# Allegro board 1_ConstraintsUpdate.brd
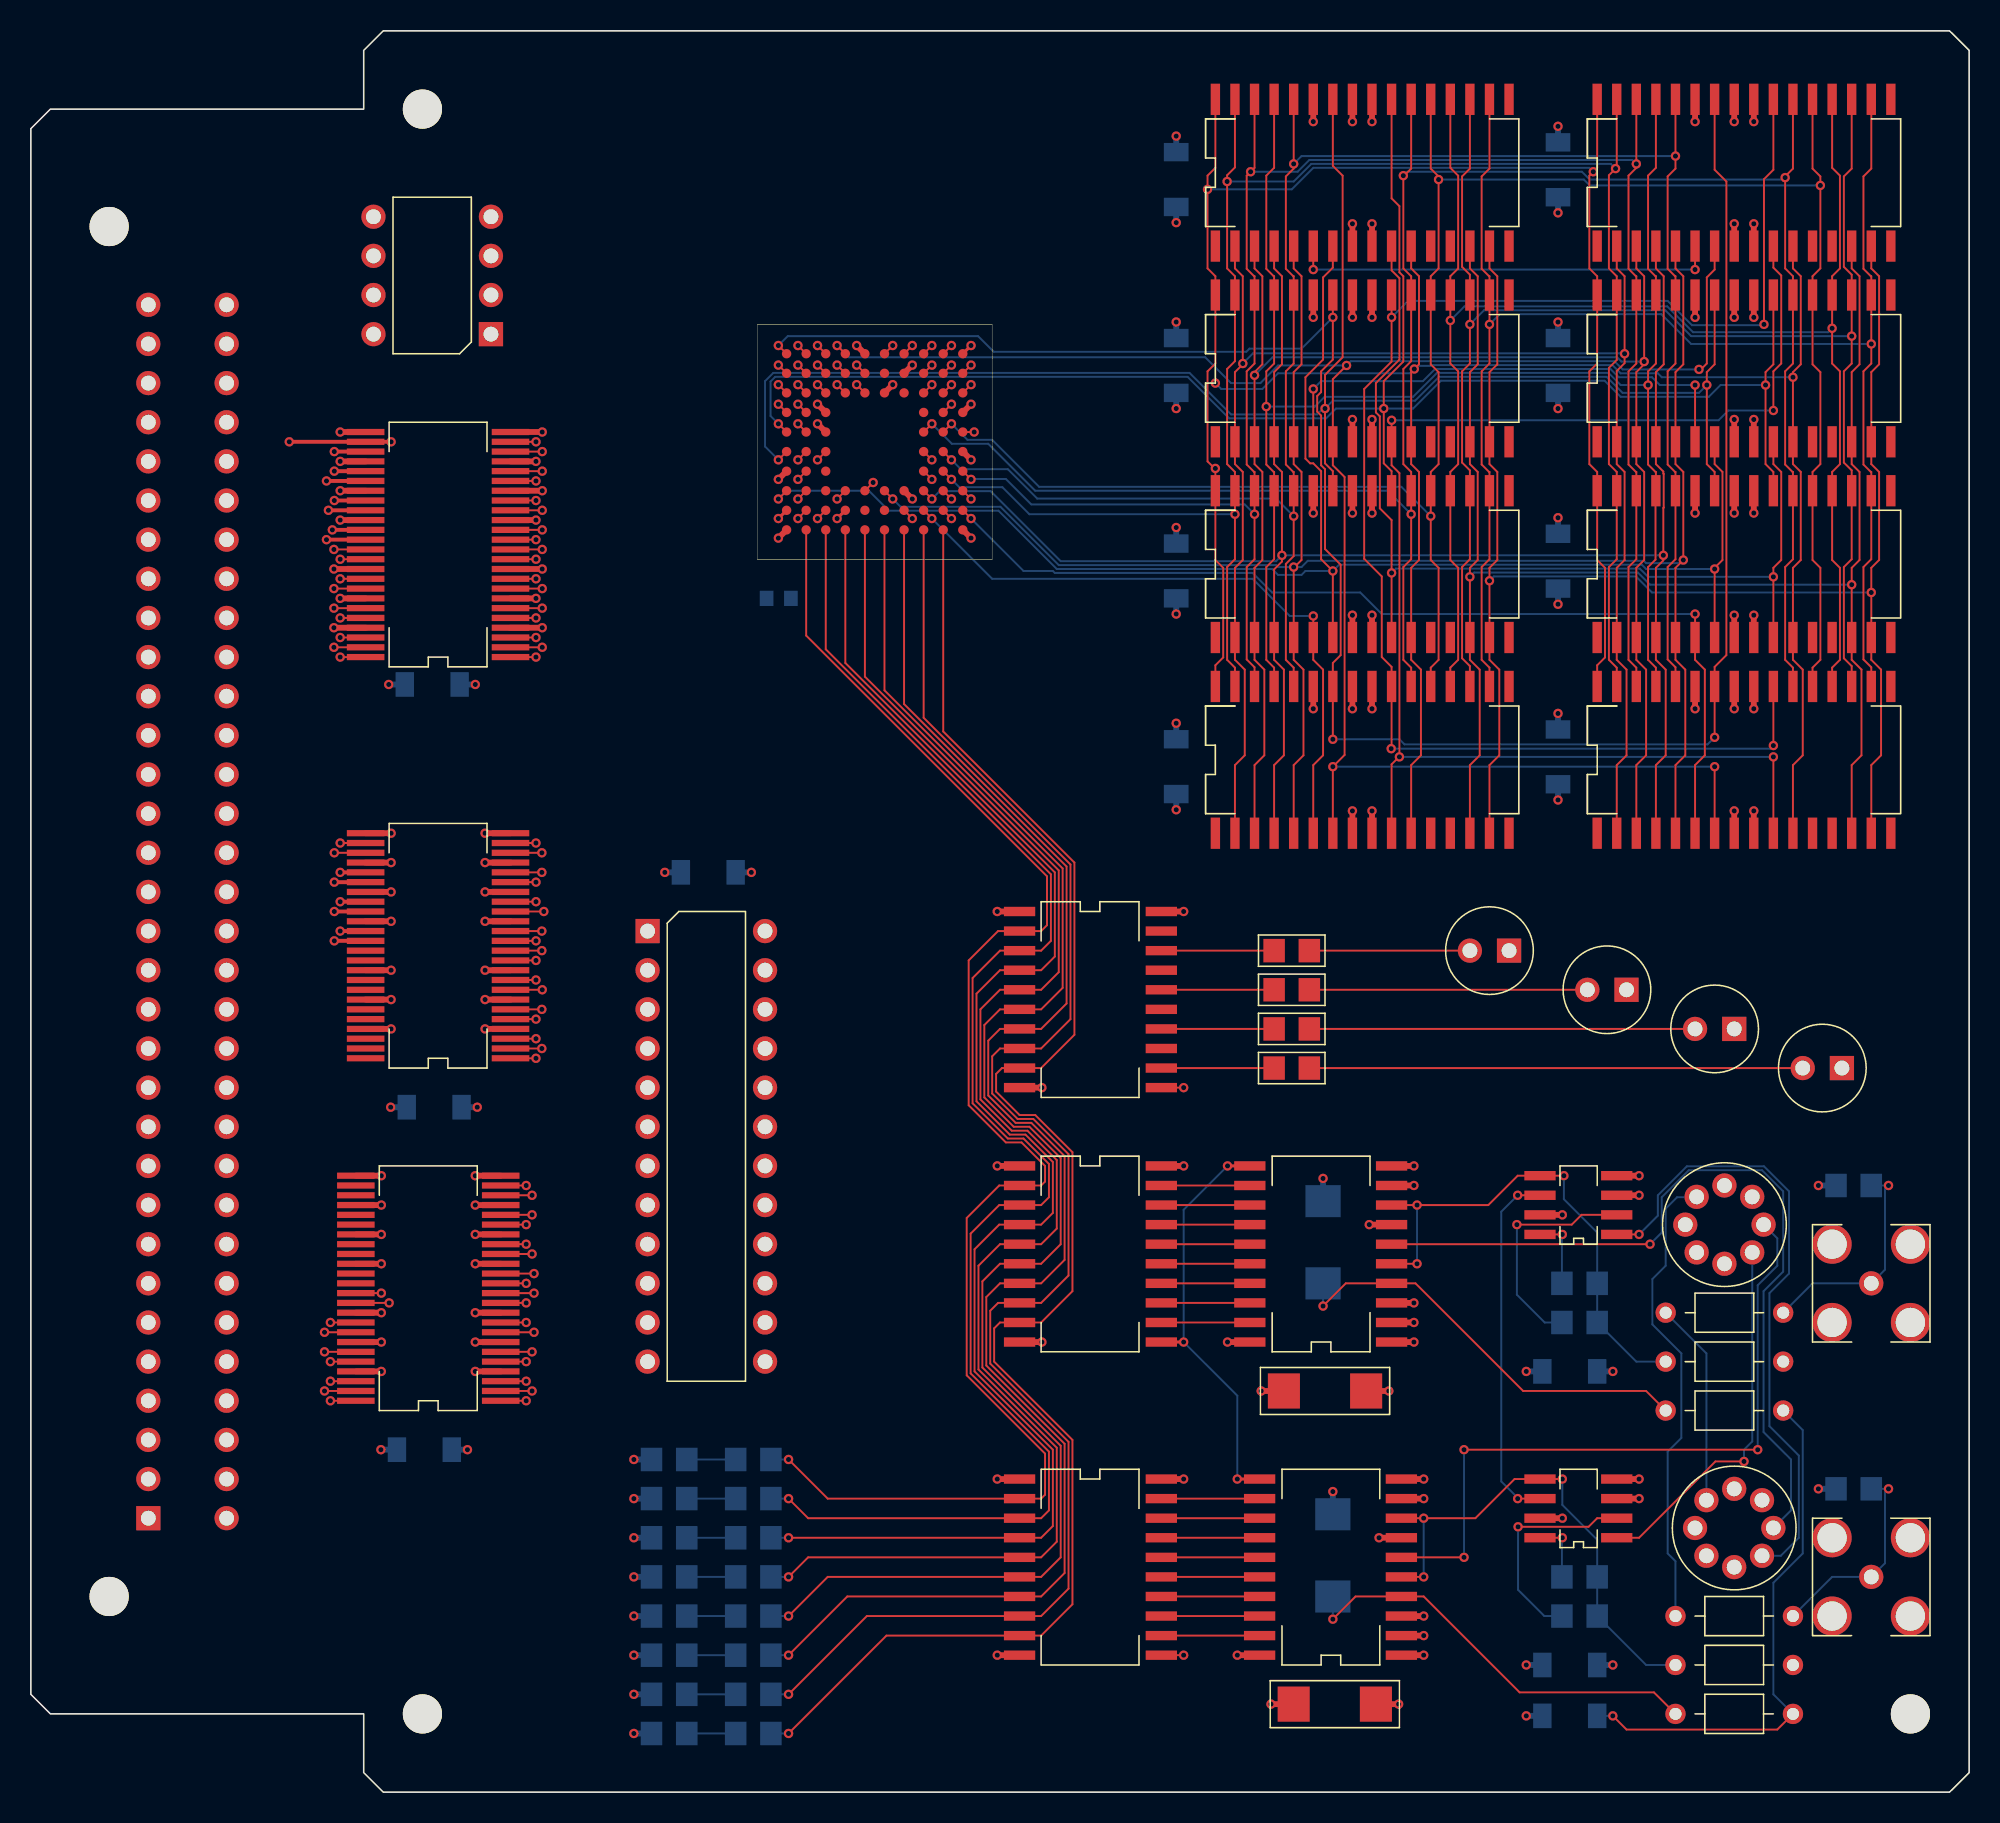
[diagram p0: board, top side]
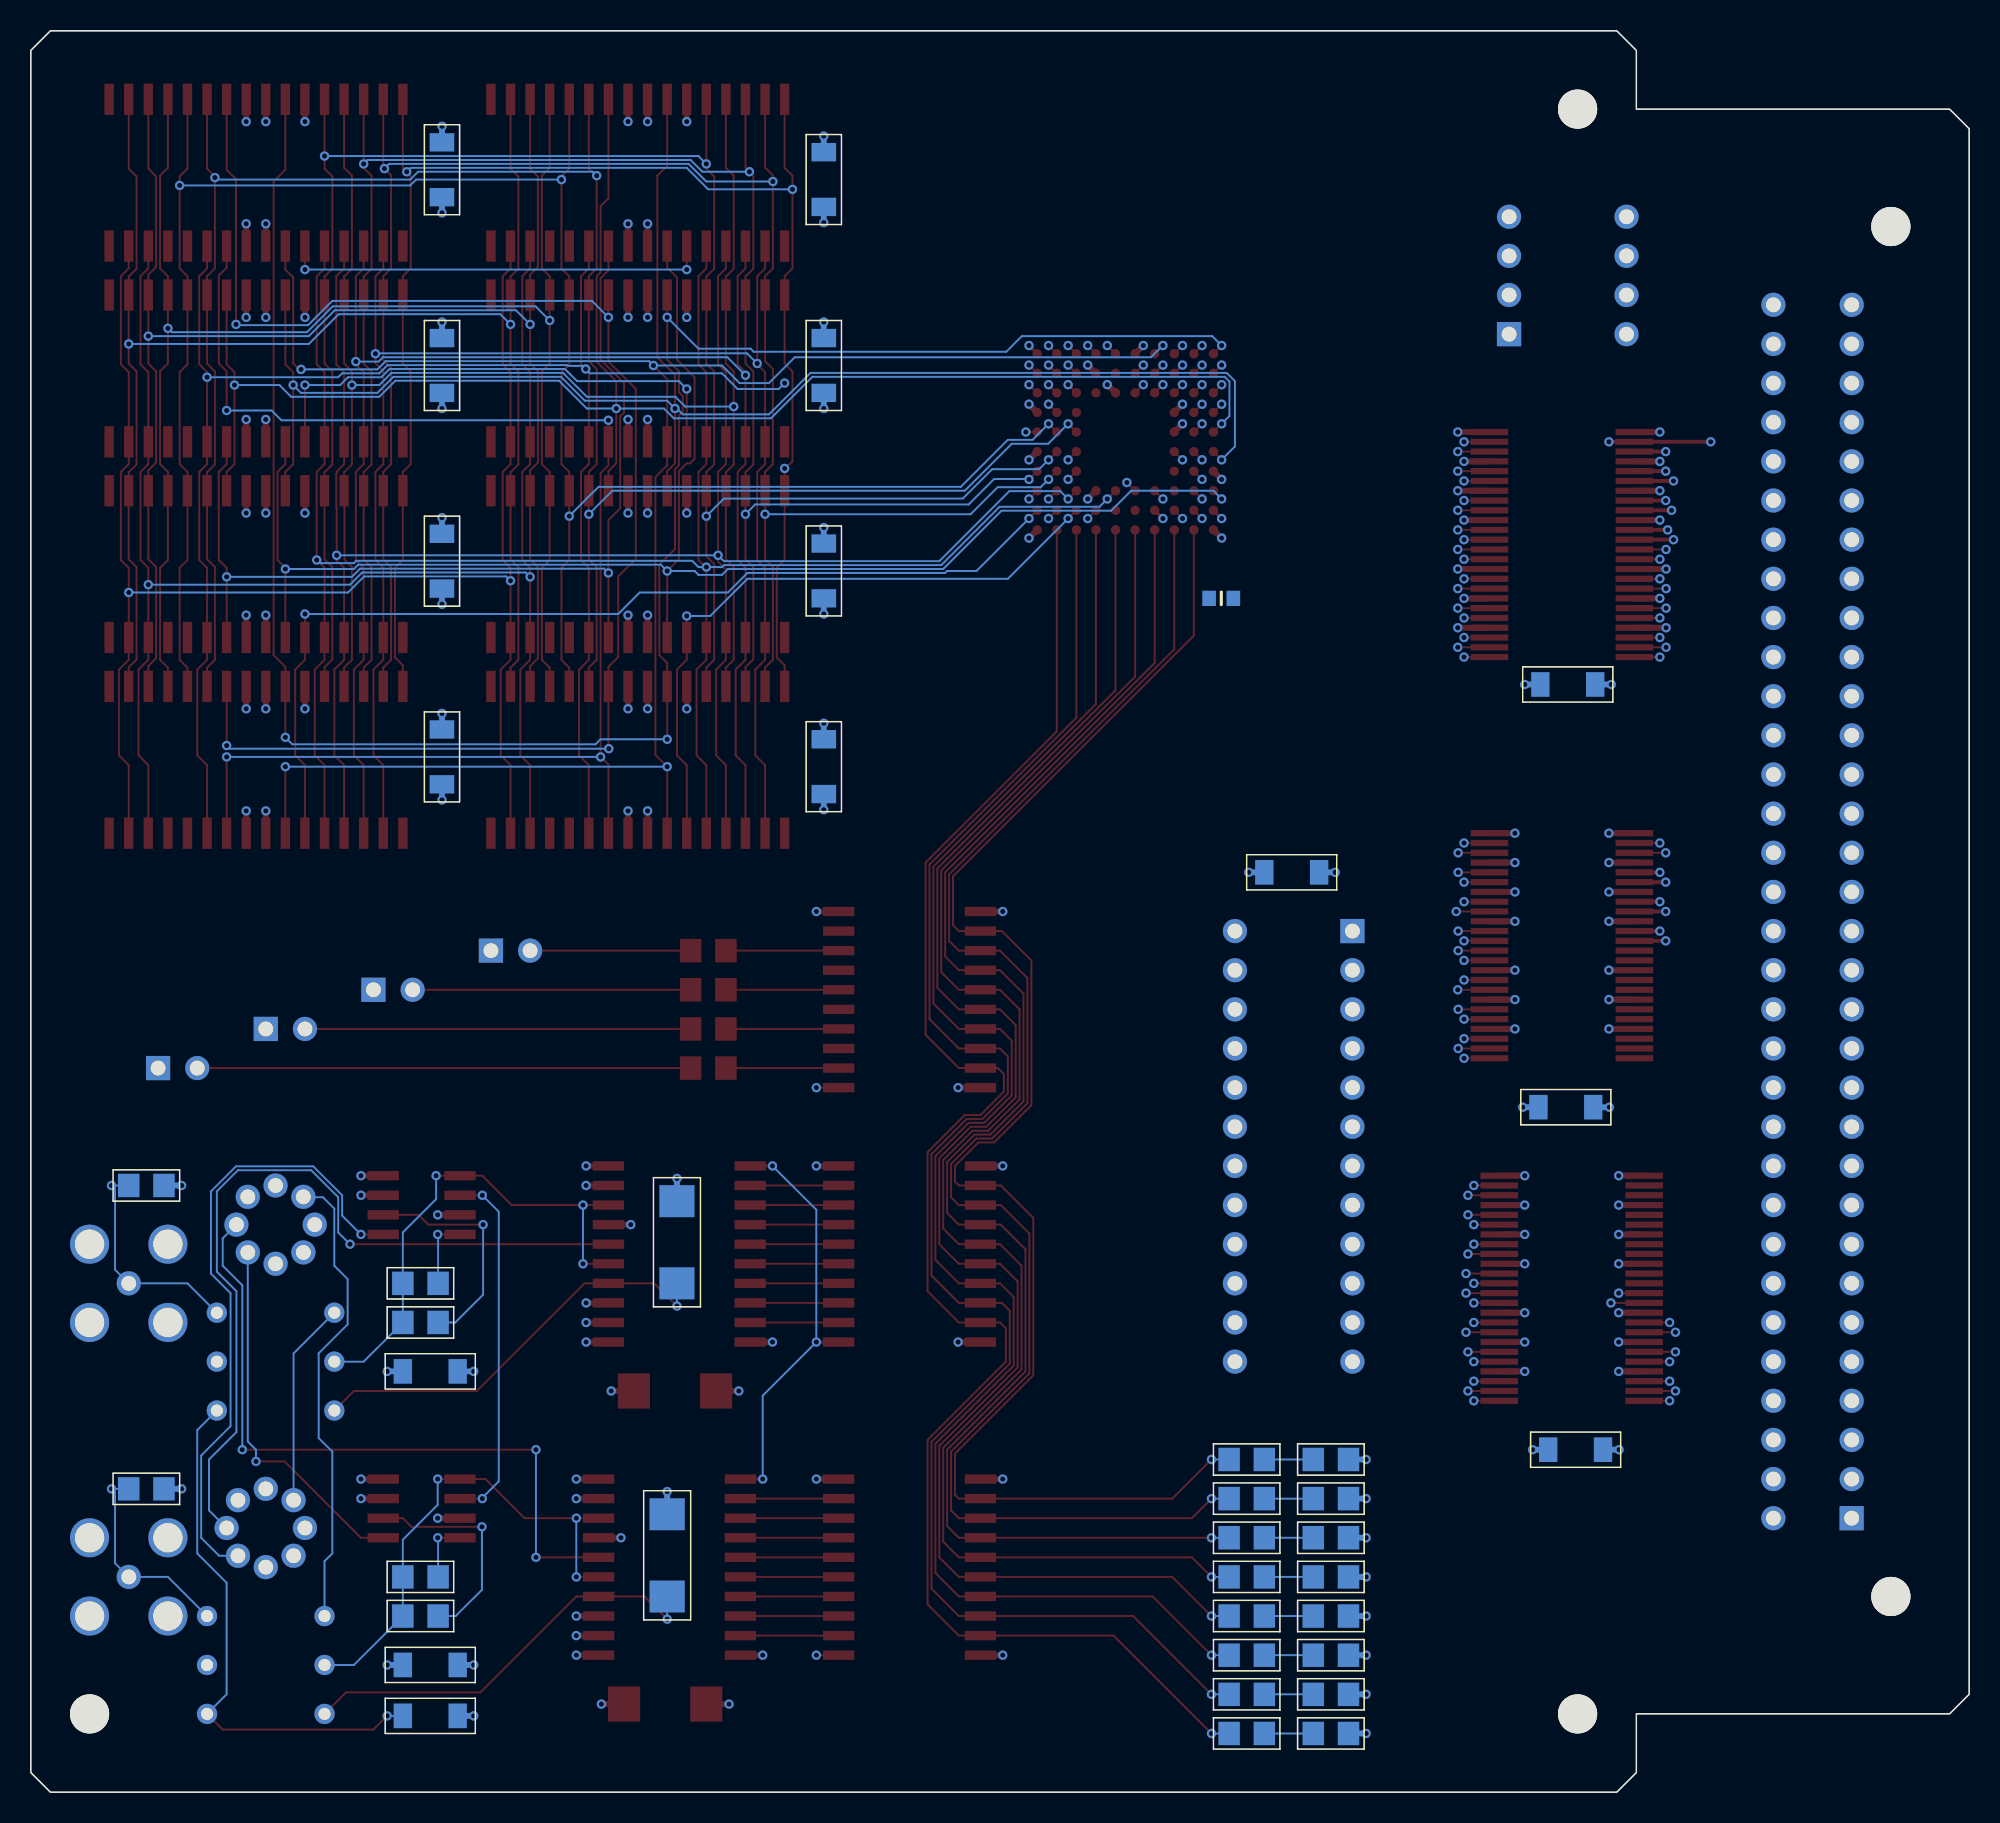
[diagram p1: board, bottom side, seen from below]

Outline 125.73 x 114.3 mm; copper layers: TOP, GND, INNER_1, INNER_2, VCC, BOTTOM. Coordinates in mm from the lower left corner of the outline.

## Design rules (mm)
constraint set DEFAULT: min track width 0.127
net group BNC2: nets BNC2 OUTA
net group BNC3: nets BNC3 OUTB
net group Q0: nets Q0 Q1
net group Q2: nets Q2 Q3
net group Q4: nets Q4 Q5
net group Q6: nets Q6 Q7
net group VCLKC: nets N1626465 VCLKC
net group VD0: nets N14855 VD0
net group VD1: nets N14853 VD1
net group VD2: nets N14849 VD2
net group VD3: nets N14843 VD3
net group VD4: nets N15161 VD4
net group VD5: nets N15155 VD5
net group VD6: nets N15151 VD6
net group VD7: nets N15143 VD7
net group CLOCK_NETS: nets DCLK MCLK VCLKA
net group DC_NETS: nets AGND GND GND_EARTH V12N V+12 VCC
net group N00036_DATA_DAAMP: nets N00036_DATA_DAAMP N282866_DATA_DAAMP N282912_DATA_DAAMP
net group N00036_DATA_DAAMP0: nets N00036_DATA_DAAMP0 N282866_DATA_DAAMP0 N282912_DATA_DAAMP0
net group VREF: nets N00038_DATA_DAAMP N00038_DATA_DAAMP0 VREF

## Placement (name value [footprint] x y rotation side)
C1  0.1uF  [SM_1206]  27.3 22.23 180 bottom
C2  0.1uF  [SM_1206]  27.94 44.45 180 bottom
C3  0.1uF  [SM_1206]  27.81 71.88 180 bottom
C4  0.1uF  [SM_1206]  45.72 59.69 180 bottom
C5  47PF  [SM_0805]  119.38 39.37 180 bottom
C6  47PF  [SM_0805]  119.38 19.69 180 bottom
C7  3300  [SM_0805]  42.55 6.35 180 bottom
C8  3300  [SM_0805]  42.55 11.43 180 bottom
C9  3300  [SM_0805]  42.55 16.51 180 bottom
C10  3300  [SM_0805]  42.55 21.59 180 bottom
C11  3300  [SM_0805]  42.55 3.81 180 bottom
C12  3300  [SM_0805]  42.55 8.89 180 bottom
C13  3300  [SM_0805]  42.55 13.97 180 bottom
C14  3300  [SM_0805]  42.55 19.05 180 bottom
C15  0.1uF  [SM_1206]  99.06 103.5 90 bottom
C16  0.1uF  [SM_1206]  99.06 78.11 90 bottom
C17  0.1uF  [SM_1206]  99.06 90.8 90 bottom
C18  0.1uF  [SM_1206]  74.3 102.87 90 bottom
C19  0.1uF  [SM_1206]  99.06 65.41 90 bottom
C20  0.1uF  [SM_1206]  74.3 90.8 90 bottom
C21  0.1uF  [SM_1206]  74.3 77.47 90 bottom
C22  0.1uF  [SM_1206]  74.3 64.77 90 bottom
C23  .01uF  [SMC_6032]  81.28 26.03 0 top
C24  .01uF  [SMC_6032]  83.82 33.02 90 bottom
C25  0.1uF  [SM_1206]  101.6 27.3 180 bottom
C26  .01uF  [SMC_6032]  81.91 5.71 0 top
C27  .01uF  [SMC_6032]  84.45 12.7 90 bottom
C28  0.1uF  [SM_1206]  101.6 8.25 180 bottom
D1  -  [LED]  95.88 54.61 180 top
D2  -  [LED]  103.5 52.07 180 top
D3  -  [LED]  110.49 49.53 180 top
D4  -  [LED]  117.47 46.99 180 top
J1  CON64  [DIN64]  7.62 17.78 0 top
J2  -  [BNC]  119.38 33.02 0 top
J3  -  [BNC]  119.38 13.97 0 top
L1  50  [IND300]  106.04 31.12 0 top
L2  50  [IND300]  106.68 11.43 0 top
L3  50  [IND300]  113.66 24.77 180 top
L4  50  [IND300]  113.66 27.94 180 top
L5  50  [IND300]  114.3 5.08 180 top
L6  50  [IND300]  114.3 8.25 180 top
NOREF  -  [unnamed]  25.4 5.08 0 top
NOREF#2  -  [#2]  259.08 129.54 0 top
NOREF#3  -  [#2]  -30.48 -55.88 0 top
R1  150  [SM_0805]  80.64 54.61 0 top
R2  150  [SM_0805]  80.64 52.07 0 top
R3  150  [SM_0805]  80.64 49.53 0 top
R4  150  [SM_0805]  80.64 46.99 0 top
R5  3.32 kOhm  [RESC1608X55N]  48.51 77.47 180 bottom
R6  10K  [SM_0805]  45.72 6.35 0 bottom
R7  10K  [SM_0805]  45.72 11.43 0 bottom
R8  10K  [SM_0805]  45.72 16.51 0 bottom
R9  10K  [SM_0805]  45.72 21.59 0 bottom
R10  10K  [SM_0805]  45.72 3.81 0 bottom
R11  10K  [SM_0805]  45.72 8.89 0 bottom
R12  10K  [SM_0805]  45.72 13.97 0 bottom
R13  10K  [SM_0805]  45.72 19.05 0 bottom
R14  1/4w  [SM_1206]  101.6 4.95 180 bottom
R15  100  [SM_0805]  101.6 30.48 180 bottom
R16  100  [SM_0805]  101.6 33.02 180 bottom
R17  100  [SM_0805]  101.6 13.97 180 bottom
R18  100  [SM_0805]  101.6 11.43 180 bottom
U1  FCT16245  [SOIC48]  30.48 25.4 180 top
U2  20L10  [DIP24]  40 55.88 0 top
U3  FCT16245  [SOIC48]  31.11 47.62 180 top
U4  FCT16245  [SOIC48]  31.11 73.66 180 top
U5  EPF8282A_BGA  [BGA_84]  54.74 87.63 0 top
U6  74ACT574  [SOIC20]  64.13 57.15 0 top
U7  EPC1064  [DIP8]  29.84 94.61 180 top
U8  74ACT574  [SOIC20]  64.13 40.64 0 top
U9  74ACT574  [SOIC20]  64.13 20.32 0 top
U10  TC55B4257  [SOIC32]  76.84 62.23 90 top
U11  TC55B4257  [SOIC32]  101.6 100.33 90 top
U12  TC55B4257  [SOIC32]  101.6 62.23 90 top
U13  TC55B4257  [SOIC32]  76.84 87.63 90 top
U14  TC55B4257  [SOIC32]  76.84 74.93 90 top
U15  TC55B4257  [SOIC32]  76.84 100.33 90 top
U16  TC55B4257  [SOIC32]  101.6 74.93 90 top
U17  TC55B4257  [SOIC32]  101.6 87.63 90 top
U18  TLC5602A  [SOIC20]  88.27 29.21 180 top
U19  DG419AK  [SOIC8]  102.87 36.2 180 top
U20  TLE2037A  [TO-99]  110.49 17.14 0 top
U21  TLC5602A  [SOIC20]  88.9 8.89 180 top
U22  TLE2037A  [TO-99]  109.85 36.83 0 top
U23  DG419AK  [SOIC8]  102.87 16.51 180 top

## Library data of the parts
C1-C4 = CAP NP: signal model: DEFAULT_CAPACITOR_100000pF_2_1
C5 = CAP: signal model: DEFAULT_CAPACITOR_47pF_2_1; room: CHAN1
C6 = CAP: signal model: DEFAULT_CAPACITOR_47pF_2_1; room: CHAN2
C7-C14 = CAP: signal model: DEFAULT_RESISTOR_3300OHM_2_1
C15-C22 = CAP NP: signal model: DEFAULT_CAPACITOR_100000pF_2_1; room: MEM
C23 C24 = CAP: signal model: DEFAULT_CAPACITOR_10000pF_2_1; room: CHAN1
C25 = CAP NP: signal model: DEFAULT_CAPACITOR_100000pF_2_1; room: CHAN1
C26 C27 = CAP: signal model: DEFAULT_CAPACITOR_10000pF_2_1; room: CHAN2
C28 = CAP NP: signal model: DEFAULT_CAPACITOR_100000pF_2_1; room: CHAN2
D1-D4 = PHOTODIODE
J1 = CON64
J2 = BNC: alternate symbols: (bnc1); room: CHAN1
J3 = BNC: alternate symbols: (bnc1); room: CHAN2
L1 L3 L4 = INDUCTOR: signal model: DEFAULT_RESISTOR_50OHM_2_1; room: CHAN1
L2 L5 L6 = INDUCTOR: signal model: DEFAULT_RESISTOR_50OHM_2_1; room: CHAN2
R1-R4 = R: signal model: DEFAULT_RESISTOR_150OHM_2_1; room: LED
R5 = RES: signal model: DEFAULT_RESISTOR_2000OHM_2_1
R6-R13 = R: signal model: DEFAULT_RESISTOR_10000OHM_2_1
R14 = R: signal model: DEFAULT_RESISTOR_0.25OHM_2_1; room: CHAN2
R15 R16 = R: signal model: DEFAULT_RESISTOR_100OHM_2_1; room: CHAN1
R17 R18 = R: signal model: DEFAULT_RESISTOR_100OHM_2_1; room: CHAN2
U1 U3 U4 = FCT16245
U2 = 20L10
U5 = EPF8282A/LCC_2
U6 = 74ACT574: room: LED
U7 = EPC1064
U8 = 74ACT574: room: CHAN1
U9 = 74ACT574: room: CHAN2
U10-U17 = TC55B4257: room: MEM
U18 = TLC5602A: room: CHAN1
U19 = DG419AK: room: CHAN1
U20 = TLE2037A: room: CHAN1
U21 = TLC5602A: room: CHAN2
U22 = TLE2037A: room: CHAN2
U23 = DG419AK: room: CHAN2

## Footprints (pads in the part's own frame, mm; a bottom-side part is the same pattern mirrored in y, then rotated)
BGA_84
  round 0.61 smd: A1(-5.715,5.715) A2(-4.445,5.715) A3(-3.175,5.715) A4(-1.905,5.715) A5(-0.635,5.715) A6(0.635,5.715) A7(1.905,5.715) A8(3.175,5.715) A9(4.445,5.715) A10(5.715,5.715) B1(-5.715,4.445) B2(-4.445,4.445) B3(-3.175,4.445) B4(-1.905,4.445) B5(-0.635,4.445) B6(0.635,4.445) B7(1.905,4.445) B8(3.175,4.445) B9(4.445,4.445) B10(5.715,4.445) C1(-5.715,3.175) C2(-4.445,3.175) C3(-3.175,3.175) C4(-1.905,3.175) C5(-0.635,3.175) C6(0.635,3.175) C7(1.905,3.175) C8(3.175,3.175) C9(4.445,3.175) C10(5.715,3.175) D1(-5.715,1.905) D2(-4.445,1.905) D3(-3.175,1.905) D8(3.175,1.905) D9(4.445,1.905) D10(5.715,1.905) E1(-5.715,0.635) E2(-4.445,0.635) E3(-3.175,0.635) E8(3.175,0.635) E9(4.445,0.635) E10(5.715,0.635) F1(-5.715,-0.635) F2(-4.445,-0.635) F3(-3.175,-0.635) F8(3.175,-0.635) F9(4.445,-0.635) F10(5.715,-0.635) G1(-5.715,-1.905) G2(-4.445,-1.905) G3(-3.175,-1.905) G8(3.175,-1.905) G9(4.445,-1.905) G10(5.715,-1.905) H1(-5.715,-3.175) H2(-4.445,-3.175) H3(-3.175,-3.175) H4(-1.905,-3.175) H5(-0.635,-3.175) H6(0.635,-3.175) H7(1.905,-3.175) H8(3.175,-3.175) H9(4.445,-3.175) H10(5.715,-3.175) J1(-5.715,-4.445) J2(-4.445,-4.445) J3(-3.175,-4.445) J4(-1.905,-4.445) J5(-0.635,-4.445) J6(0.635,-4.445) J7(1.905,-4.445) J8(3.175,-4.445) J9(4.445,-4.445) J10(5.715,-4.445) K1(-5.715,-5.715) K2(-4.445,-5.715) K3(-3.175,-5.715) K4(-1.905,-5.715) K5(-0.635,-5.715) K6(0.635,-5.715) K7(1.905,-5.715) K8(3.175,-5.715) K9(4.445,-5.715) K10(5.715,-5.715)
BNC
  round 1.575 hole 0.965: 1(0,0)
  round 2.54 hole 1.905: 2(-2.54,2.54) 3(-2.54,-2.54) 4(2.54,2.54) 5(2.54,-2.54)
DIN64
  round 2.54 hole 2.794 unplated: (-2.54,83.82) (-2.54,-5.08)
  rect 1.575x1.575 hole 0.965: 1(0,0)
  round 1.575 hole 0.965: 2(0,2.54) 3(0,5.08) 4(0,7.62) 5(0,10.16) 6(0,12.7) 7(0,15.24) 8(0,17.78) 9(0,20.32) 10(0,22.86) 11(0,25.4) 12(0,27.94) 13(0,30.48) 14(0,33.02) 15(0,35.56) 16(0,38.1) 17(0,40.64) 18(0,43.18) 19(0,45.72) 20(0,48.26) 21(0,50.8) 22(0,53.34) 23(0,55.88) 24(0,58.42) 25(0,60.96) 26(0,63.5) 27(0,66.04) 28(0,68.58) 29(0,71.12) 30(0,73.66) 31(0,76.2) 32(0,78.74) 33(5.08,0) 34(5.08,2.54) 35(5.08,5.08) 36(5.08,7.62) 37(5.08,10.16) 38(5.08,12.7) 39(5.08,15.24) 40(5.08,17.78) 41(5.08,20.32) 42(5.08,22.86) 43(5.08,25.4) 44(5.08,27.94) 45(5.08,30.48) 46(5.08,33.02) 47(5.08,35.56) 48(5.08,38.1) 49(5.08,40.64) 50(5.08,43.18) 51(5.08,45.72) 52(5.08,48.26) 53(5.08,50.8) 54(5.08,53.34) 55(5.08,55.88) 56(5.08,58.42) 57(5.08,60.96) 58(5.08,63.5) 59(5.08,66.04) 60(5.08,68.58) 61(5.08,71.12) 62(5.08,73.66) 63(5.08,76.2) 64(5.08,78.74)
DIP8
  rect 1.575x1.575 hole 0.965: 1(0,0)
  round 1.575 hole 0.965: 2(0,-2.54) 3(0,-5.08) 4(0,-7.62) 5(7.62,-7.62) 6(7.62,-5.08) 7(7.62,-2.54) 8(7.62,0)
DIP24
  rect 1.575x1.575 hole 0.965: 1(0,0)
  round 1.575 hole 0.965: 2(0,-2.54) 3(0,-5.08) 4(0,-7.62) 5(0,-10.16) 6(0,-12.7) 7(0,-15.24) 8(0,-17.78) 9(0,-20.32) 10(0,-22.86) 11(0,-25.4) 12(0,-27.94) 13(7.62,-27.94) 14(7.62,-25.4) 15(7.62,-22.86) 16(7.62,-20.32) 17(7.62,-17.78) 18(7.62,-15.24) 19(7.62,-12.7) 20(7.62,-10.16) 21(7.62,-7.62) 22(7.62,-5.08) 23(7.62,-2.54) 24(7.62,0)
IND300
  round 1.321 hole 0.787: 1(0,0) 2(7.62,0)
LED
  rect 1.575x1.575 hole 0.965: 1(0,0)
  round 1.575 hole 0.965: 2(2.54,0)
RESC1608X55N
  rect 0.889x0.991 smd: 1(-0.787,0) 2(0.787,0)
SM_0805
  rect 1.397x1.524 smd: 1(0,0) 2(2.286,0)
SM_1206
  rect 1.194x1.6 smd: 1(0,0) 2(3.556,0)
SMC_6032
  rect 2.083x2.286 smd: 1(0,0) 2(5.334,0)
SOIC8
  rect 2.032x0.61 smd: 1(0,0) 2(0,-1.27) 3(0,-2.54) 4(0,-3.81) 5(4.978,-3.81) 6(4.978,-2.54) 7(4.978,-1.27) 8(4.978,0)
SOIC20
  rect 2.032x0.61 smd: 1(0,0) 2(0,-1.27) 3(0,-2.54) 4(0,-3.81) 5(0,-5.08) 6(0,-6.35) 7(0,-7.62) 8(0,-8.89) 9(0,-10.16) 10(0,-11.43) 11(9.195,-11.43) 12(9.195,-10.16) 13(9.195,-8.89) 14(9.195,-7.62) 15(9.195,-6.35) 16(9.195,-5.08) 17(9.195,-3.81) 18(9.195,-2.54) 19(9.195,-1.27) 20(9.195,0)
SOIC32
  rect 2.032x0.61 smd: 1(0,0) 2(0,-1.27) 3(0,-2.54) 4(0,-3.81) 5(0,-5.08) 6(0,-6.35) 7(0,-7.62) 8(0,-8.89) 9(0,-10.16) 10(0,-11.43) 11(0,-12.7) 12(0,-13.97) 13(0,-15.24) 14(0,-16.51) 15(0,-17.78) 16(0,-19.05) 17(9.525,-19.05) 18(9.525,-17.78) 19(9.525,-16.51) 20(9.525,-15.24) 21(9.525,-13.97) 22(9.525,-12.7) 23(9.525,-11.43) 24(9.525,-10.16) 25(9.525,-8.89) 26(9.525,-7.62) 27(9.525,-6.35) 28(9.525,-5.08) 29(9.525,-3.81) 30(9.525,-2.54) 31(9.525,-1.27) 32(9.525,0)
SOIC48
  rect 2.438x0.406 smd: 1(0,0) 2(0,-0.635) 3(0,-1.27) 4(0,-1.905) 5(0,-2.54) 6(0,-3.175) 7(0,-3.81) 8(0,-4.445) 9(0,-5.08) 10(0,-5.715) 11(0,-6.35) 12(0,-6.985) 13(0,-7.62) 14(0,-8.255) 15(0,-8.89) 16(0,-9.525) 17(0,-10.16) 18(0,-10.795) 19(0,-11.43) 20(0,-12.065) 21(0,-12.7) 22(0,-13.335) 23(0,-13.97) 24(0,-14.605) 25(9.398,-14.605) 26(9.398,-13.97) 27(9.398,-13.335) 28(9.398,-12.7) 29(9.398,-12.065) 30(9.398,-11.43) 31(9.398,-10.795) 32(9.398,-10.16) 33(9.398,-9.525) 34(9.398,-8.89) 35(9.398,-8.255) 36(9.398,-7.62) 37(9.398,-6.985) 38(9.398,-6.35) 39(9.398,-5.715) 40(9.398,-5.08) 41(9.398,-4.445) 42(9.398,-3.81) 43(9.398,-3.175) 44(9.398,-2.54) 45(9.398,-1.905) 46(9.398,-1.27) 47(9.398,-0.635) 48(9.398,0)
TO-99
  round 1.575 hole 0.965: 1(0,-2.54) 2(1.803,-1.803) 3(2.54,0) 4(1.803,1.803) 5(0,2.54) 6(-1.803,1.803) 7(-2.54,0) 8(-1.803,-1.803)
unnamed
  round 2.54 hole 2.794 unplated: (0,104.14) (0,0) (96.52,0)

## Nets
AGND: C24.2 C25.2 C27.2 C28.2 J1.34 J1.35 J1.36 U18.3 U18.7 U18.10 U19.3 U21.3 U21.7 U21.10 U23.3
GND: C1.2 C2.2 C3.2 C4.2 C7.2 C8.2 C9.2 C10.2 C11.2 C12.2 C13.2 C14.2 C15.2 C16.2 C17.2 C18.2 C19.2 C20.2 C21.2 C22.2 C23.2 C26.2 J1.1 J1.2 J1.3 J1.33 R14.2 U1.4 U1.10 U1.15 U1.21 U1.24 U1.25(G\) U1.28 U1.34 U1.39 U1.45 U2.11 U2.12 U2.13 U3.4 U3.10 U3.15 U3.21 U3.24 U3.25(G\) U3.28 U3.34 U3.39 U3.45 U4.4 U4.10 U4.15 U4.21 U4.24 U4.25(G\) U4.28 U4.34 U4.39 U4.45 U5.A5 U5.C6 U5.D3 U5.D10 U5.E3 U5.F10 U5.K10 U6.1 U6.10 U7.5 U8.1 U8.10 U9.1 U9.10 U10.9 U10.25 U10.27 U11.9 U11.25 U11.27 U12.9 U12.25 U12.27 U13.9 U13.25 U13.27 U14.9 U14.25 U14.27 U15.9 U15.25 U15.27 U16.9 U16.25 U16.27 U17.9 U17.25 U17.27 U18.1 U18.20 U21.1 U21.20
GND_EARTH: C5.2 C6.2 J2.2 J2.3 J2.4 J2.5(GND5) J3.2 J3.3 J3.4 J3.5(GND5)
V12N: J1.31 J1.32 U19.7 U20.4(V-) U22.4(V-) U23.7
VCC: C1.1 C2.1 C3.1 C4.1 C15.1 C16.1 C17.1 C18.1 C19.1 C20.1 C21.1 C22.1 C23.1 C26.1 D1.1 D2.1 D3.1 D4.1 J1.29 J1.30 J1.62 L4.1 L6.1 U1.7 U1.18 U1.31 U1.42 U2.24(VCC) U3.7 U3.18 U3.31 U3.42 U4.7 U4.18 U4.31 U4.42 U5.B7 U5.G1 U5.H7 U5.K1 U6.20 U7.7 U7.8 U8.20 U9.20 U10.8 U10.24 U11.8 U11.24 U12.8 U12.24 U13.8 U13.24 U14.8 U14.24 U15.8 U15.24 U16.8 U16.24 U17.8 U17.24 U18.2 U18.9(VD2) U21.2 U21.9(VD2)
A0: J1.54 U4.47
A1: J1.55 U4.46
A2: J1.56 U4.44
A3: J1.57 U4.43
A4: J1.58 U4.41
A5: J1.59 U4.40
A6: J1.60 U4.38
A7: J1.61 U4.37
AD0: J1.37 U1.47
AD1: J1.38 U1.46
AD2: J1.39 U1.44 U2.6
AD3: J1.40 U1.43 U2.5
AD4: J1.41 U1.41 U2.4
AD5: J1.42 U1.40 U2.3
AD6: J1.43 U1.38 U2.2
AD7: J1.44 U1.37 U2.1
AEN: J1.47 U2.8
BA0: U1.13 U3.13 U4.13 U5.A6
BA1: U1.14 U3.14 U4.14 U5.A7
BA2: U1.16 U3.16 U4.16 U5.A8
BA3: U1.17 U3.17 U4.17 U5.A9
BA4: U1.19 U3.19 U4.19
BA5: U1.20 U3.20 U4.20
BA6: U1.22 U3.22 U4.22
BA7: U1.23 U3.23 U4.23
BD0: U4.12 U5.C5
BD1: U4.11 U5.C4
BD2: U4.9 U5.C3
BD3: U4.8 U5.C2
BD4: U4.6 U5.C1
BD5: U4.5 U5.B10
BD6: U4.3 U5.B9
BD7: U4.2 U5.B8
BD8: U1.12 U3.2
BD9: U1.11 U3.3
BD10: U1.9 U3.5
BD11: U1.8 U3.6
BD12: U1.6 U3.8
BD13: U1.5 U3.9
BD14: U1.3 U3.11
BD15: U1.2 U3.12
BNC2: C5.1 J2.1 L1.2
BNC3: C6.1 J3.1 L2.2
BRD: U2.16 U5.D9
BRESET: U2.15 U5.B2
BWR: U2.17 U5.H2
C_DAT1_N: J1.13 U3.47
C_DAT1_P: J1.14 U3.46
C_DAT2_N: J1.15 U3.44
C_DAT2_P: J1.16 U3.43
C_DAT3_N: J1.17 U3.41
C_DAT3_P: J1.18 U3.40
C_DAT4_N: J1.19 U3.38
C_DAT4_P: J1.20 U3.37
D0: J1.28 U3.26 U4.26
D1: J1.27 U3.27 U4.27
D2: J1.26 U3.29 U4.29
D3: J1.25 U3.30 U4.30
D4: J1.24 U3.32 U4.32
D5: J1.23 U3.33 U4.33
D6: J1.22 U3.35 U4.35
D7: J1.21 U3.36 U4.36
DATA: U5.B4 U7.1
DCLK: U5.A10 U7.2
DDIR: U1.48 U2.20 U3.48 U4.48
DEN: U1.1 U2.21 U4.1
DHEN: U2.22 U3.1
FPGA: U2.18 U5.C10
GAIN: U5.C8 U19.6 U23.6
HS: U2.19 U5.C9
MCLK: J1.52 U5.J1
MRD: J1.46 U2.9
MWR: J1.45 U2.10
N00036_DATA_DAAMP: L4.2 R15.1 R16.1 U18.5 U18.8 U19.5(VL)
N00036_DATA_DAAMP0: L6.2 R17.1 R18.1 U21.5 U21.8 U23.5(VL)
N00038_DATA_DAAMP: C24.1 L3.2 U18.4
N00038_DATA_DAAMP0: C27.1 L5.2 U21.4
N00044_DATA_DAAMP: U19.1 U20.2
N00044_DATA_DAAMP0: U22.2 U23.1
N00060_DATA_DAAMP: U18.6 U20.3
N00060_DATA_DAAMP0: U21.6 U22.3
N282866_DATA_DAAMP: R16.2 U19.8
N282866_DATA_DAAMP0: R17.2 U23.8
N282912_DATA_DAAMP: R15.2 U19.2
N282912_DATA_DAAMP0: R18.2 U23.2
NCS: U5.B1 U7.4
OE: U5.J2 U7.3(OE)
OUTA: L1.1 U20.6
OUTB: L2.1 U22.6
Q0: R4.1 U6.12(Q8)
Q1: D4.2(CATHODE) R4.2
Q2: R3.1 U6.14
Q3: D3.2(CATHODE) R3.2
Q4: R2.1 U6.16
Q5: D2.2(CATHODE) R2.2
Q6: R1.1 U6.18
Q7: D1.2(CATHODE) R1.2
RA0: U5.H6 U10.5 U11.5 U12.5 U13.5 U14.5 U15.5 U16.5 U17.5
RA1: U5.H8 U10.4 U11.4 U12.4 U13.4 U14.4 U15.4 U16.4 U17.4
RA2: U5.H9 U10.3 U11.3 U12.3 U13.3 U14.3 U15.3 U16.3 U17.3
RA3: U5.H10 U10.2 U11.2 U12.2 U13.2 U14.2 U15.2 U16.2 U17.2
RA4: U5.G8 U10.32 U11.32 U12.32 U13.32 U14.32 U15.32 U16.32 U17.32
RA5: U5.G9 U10.31 U11.31 U12.31 U13.31 U14.31 U15.31 U16.31 U17.31
RA6: U5.G10 U10.30 U11.30 U12.30 U13.30 U14.30 U15.30 U16.30 U17.30
RA7: U5.F8 U10.29 U11.29 U12.29 U13.29 U14.29 U15.29 U16.29 U17.29
RA8: U5.F9 U10.28 U11.28 U12.28 U13.28 U14.28 U15.28 U16.28 U17.28
RA9: U5.E8 U10.22 U11.22 U12.22 U13.22 U14.22 U15.22 U16.22 U17.22
RA10: U5.E9 U10.21 U11.21 U12.21 U13.21 U14.21 U15.21 U16.21 U17.21
RA11: U5.E10 U10.20 U11.20 U12.20 U13.20 U14.20 U15.20 U16.20 U17.20
RA12: U5.G2 U10.19 U11.19 U12.19 U13.19 U14.19 U15.19 U16.19 U17.19
RA13: U5.F2 U10.18 U11.18 U12.18 U13.18 U14.18 U15.18 U16.18 U17.18
RA14: U5.E2 U10.15 U11.15 U12.15 U13.15 U14.15 U15.15 U16.15 U17.15
RA15: U5.D2 U10.14 U11.14 U12.14 U13.14 U14.14 U15.14 U16.14 U17.14
RCS0: U5.J8 U10.6 U14.6
RCS1: U5.J9 U11.6 U15.6
RCS2: U5.J10 U12.6 U16.6
RCS3: U5.F3 U13.6 U17.6
RD0: U5.F1 U14.26 U15.26 U16.26 U17.26
RD1: U5.E1 U14.23 U15.23 U16.23 U17.23
RD2: U5.D1 U14.10 U15.10 U16.10 U17.10
RD3: U5.H1 U14.7 U15.7 U16.7 U17.7
RD4: U5.A1 U10.26 U11.26 U12.26 U13.26
RD5: U5.A2 U10.23 U11.23 U12.23 U13.23
RD6: U5.A3 U10.10 U11.10 U12.10 U13.10
RD7: U5.A4 U10.7 U11.7 U12.7 U13.7
RDY: J1.50 U2.23
RESET: J1.53 U5.B5
RWE: U5.H5 U10.11(W\E\) U11.11(W\E\) U12.11(W\E\) U13.11(W\E\) U14.11(W\E\) U15.11(W\E\) U16.11(W\E\) U17.11(W\E\)
RX_DAT1_N: J1.4 U1.36
RX_DAT1_P: J1.5 U1.35
RX_DAT2_N: J1.6 U1.33
RX_DAT2_P: J1.7 U1.32
RX_DAT3_N: J1.8 U1.30
RX_DAT3_P: J1.9 U1.29
RX_DAT4_N: J1.10 U1.27
RX_DAT4_P: J1.11 U1.26
SEL: U2.14 U5.B3
V+12: C25.1 C28.1 J1.63 J1.64 U19.4 U20.7 U22.7 U23.4
VCLKA: U5.J4 U8.11 U18.11 U21.11
VCLKC: R5.2 U9.11
VD0: R9.2 U5.K2 U6.2 U8.2 U9.2
VD1: R13.2 U5.K3 U6.3 U8.3 U9.3
VD2: R8.2 U5.K4 U6.4 U8.4 U9.4
VD3: R12.2 U5.K5 U6.5 U8.5 U9.5
VD4: R7.2 U5.K6 U6.6 U8.6 U9.6
VD5: R11.2 U5.K7 U6.7 U8.7 U9.7
VD6: R6.2 U5.K8 U6.8 U8.8 U9.8
VD7: R10.2 U5.K9(VD7) U6.9 U8.9 U9.9
VREF: L3.1 L5.1 R14.1
WAIT: J1.51 U5.J3
WSTAT: U5.H4 U6.11
N14843: C13.1 R12.1
N14849: C9.1 R8.1
N14853: C14.1 R13.1
N14855: C10.1 R9.1
N15143: C11.1 R10.1
N15151: C7.1 R6.1
N15155: C12.1 R11.1
N15161: C8.1 R7.1
N58063: U8.19 U18.12
N58118: U8.18 U18.13
N58173: U8.17 U18.14
N58228: U8.16 U18.15
N58283: U8.15 U18.16
N58338: U8.14 U18.17
N58393: U8.13 U18.18
N58448: U8.12(Q8) U18.19
N58834: U9.19 U21.12
N58889: U9.18 U21.13
N58944: U9.17 U21.14
N58999: U9.16 U21.15
N59054: U9.15 U21.16
N59109: U9.14 U21.17
N59164: U9.13 U21.18
N59219: U9.12(Q8) U21.19
N1626465: R5.1 U5.J7

Pads without a net: J1 12 48 49; U2 7; U5 B6 C7 D8 G3 H3 J5 J6; U6 13 15 17 19; U7 6; U10 1 12 13 16 17; U11 1 12 13 16 17; U12 1 12 13 16 17; U13 1 12 13 16 17; U14 1 12 13 16 17; U15 1 12 13 16 17; U16 1 12 13 16 17; U17 1 12 13 16 17; U20 1 5 8; U22 1 5 8

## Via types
v1: diameter 0.61, hole 0.33, TOP to BOTTOM, 417 vias

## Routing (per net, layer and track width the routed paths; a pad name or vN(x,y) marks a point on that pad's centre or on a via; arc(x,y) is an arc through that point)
AGND: length 16.6
  TOP w0.381: U23.3 v1(104.32,19.05) ; U18.10 v1(89.71,40.64) ; U21.3 v1(90.35,11.43) ; U21.10 v1(90.35,20.32) ; U21.7 v1(87.45,16.51) ; U18.7 v1(86.82,36.83) ; U18.3 v1(89.71,31.75) ; U19.3 v1(104.32,38.73)
  BOTTOM w0.381: C25.2 v1(97,27.3) ; C24.2 v1(83.82,39.83) ; C28.2 v1(97,8.25) ; C27.2 v1(84.45,19.51)
GND: length 131.7
  TOP w0.381: U16.27 v1(107.95,83.01) ; U1.21 v1(28.83,38.1) ; U8.10 v1(65.58,29.21) ; U1.10 v1(28.83,31.12) ; 21.72,79.38 v1(19.66,79.38) ; U5.K10 v1(60.99,81.38) ; U10.25 v1(85.72,70.31) ; U9.10 v1(62.69,8.89) ; 83.19,84.45 v1(83.19,83.01) ; U6.1 v1(62.69,57.15) ; U9.1 v1(62.69,20.32) ; U3.24 v1(29.46,62.23) ; U3.4 v1(29.46,49.53) ; U1.28 v1(22.73,38.1) ; 83.19,109.86 v1(83.19,108.41) ; U3.15 v1(29.46,56.52) ; 21.72,56.52 v1(23.37,56.52) ; 87.25,5.71 v1(88.72,5.71) ; U14.25 v1(85.72,83.01) ; 21.72,75.56 v1(19.66,75.56) ; U12.27 v1(107.95,70.31) ; U1.34 v1(22.73,34.29) ; U1.15 v1(28.83,34.29) ; U17.9 v1(111.76,89.08) ; U10.9 v1(87,63.68) ; U5.E3 v1(51.03,88.8) ; U6.10 v1(65.58,45.72) ; 21.72,53.34 v1(23.37,53.34) ; U13.25 v1(85.72,95.71) ; U16.9 v1(111.76,76.38) ; C23.2 v1(88.09,26.03) ; U5.D3 v1(51.03,90.07) ; U4.10 v1(33.17,79.38) ; U11.9 v1(111.76,101.78) ; U12.25 v1(110.49,70.31) ; U1.45 v1(22.73,27.3) ; U5.C6 v1(55.91,91.34) ; U18.20 v1(77.62,29.21) ; U11.25 v1(110.49,108.41) ; U1.4 v1(28.83,27.3) ; U15.9 v1(87,101.78) ; 83.19,97.16 v1(83.19,95.71) ; U15.25 v1(85.72,108.41) ; U13.9 v1(87,89.08) ; U16.25 v1(110.49,83.01) ; U4.4 v1(33.17,75.56) ; U21.1 v1(90.35,8.89) ; U5.D10 v1(60.99,90.07) ; U17.25 v1(110.49,95.71) ; 83.19,71.75 v1(83.19,70.31) ; U5.A5 v1(53.57,93.88) ; U1.24 v1(28.83,40) ; U18.1 v1(89.71,29.21) ; U8.1 v1(62.69,40.64) ; U12.9 v1(111.76,63.68) ; U17.27 v1(107.95,95.71) ; 31.11,60.32 v1(29.46,60.32) ; 21.72,60.32 v1(23.37,60.32) ; U21.20 v1(78.26,8.89) ; U4.15 v1(32.77,82.55) ; 21.72,88.27 v1(20.07,88.27) ; U1.25 v1(22.73,40) ; 60.45,87 v1(60.99,86.46) ; U4.24 v1(33.17,88.27) ; 21.72,49.53 v1(23.37,49.53) ; U11.27 v1(107.95,108.41) ; 21.72,82.55 v1(20.07,82.55) ; U4.21 v1(32.77,86.36) ; U1.39 v1(22.73,31.12) ; U14.9 v1(87,76.38) ; U3.10 v1(29.46,53.34) ; 21.72,86.36 v1(20.07,86.36) ; 21.72,62.23 v1(23.37,62.23)
  BOTTOM w0.381: C8.2 v1(39.12,11.43) ; C13.2 v1(39.12,13.97) ; C12.2 v1(39.12,8.89) ; C10.2 v1(39.12,21.59) ; C11.2 v1(39.12,3.81) ; C17.2 v1(99.06,95.4) ; C7.2 v1(39.12,6.35) ; C16.2 v1(99.06,82.7) ; 98.04,4.95 v1(97,4.95) ; C1.2 v1(22.71,22.23) ; C3.2 v1(23.22,71.88) ; C18.2 v1(74.3,107.47) ; C19.2 v1(99.06,70) ; C20.2 v1(74.3,95.4) ; C21.2 v1(74.3,82.07) ; C2.2 v1(23.34,44.45) ; C22.2 v1(74.3,69.37) ; C9.2 v1(39.12,16.51) ; C14.2 v1(39.12,19.05) ; C4.2 v1(41.12,59.69) ; C15.2 v1(99.06,108.1)
GND_EARTH: length 2.3
  BOTTOM w0.381: C6.2 v1(115.95,19.69) ; C5.2 v1(115.95,39.37)
V12N: length 2.9
  TOP w0.381: U23.7 v1(99.34,17.78) ; U19.7 v1(99.34,37.46)
VCC: length 71.7
  TOP w0.381: U10.8 v1(85.72,63.68) ; U11.24 v1(111.76,108.41) ; U13.8 v1(85.72,89.08) ; U14.8 v1(85.72,76.38) ; U15.8 v1(85.72,101.78) ; C26.1 v1(80.44,5.71) ; U10.24 v1(87,70.31) ; U6.20 v1(74.78,57.15) ; U15.24 v1(87,108.41) ; U5.K1 v1(48.49,81.38) ; U16.24 v1(111.76,83.01) ; U16.8 v1(110.49,76.38) ; U14.24 v1(87,83.01) ; 21.72,51.43 v1(23.37,51.43) ; U1.7 v1(28.83,29.21) ; U1.42 v1(22.73,29.21) ; U12.24 v1(111.76,70.31) ; U1.18 v1(28.83,36.2) ; U3.18 v1(29.46,58.42) ; 21.72,58.42 v1(23.37,58.42) ; U12.8 v1(110.49,63.68) ; U4.18 v1(33.17,84.45) ; U18.9 v1(89.71,39.37) ; U21.9 v1(90.35,19.05) ; U9.20 v1(74.78,20.32) ; 21.72,77.47 v1(20.07,77.47) ; U1.31 v1(22.73,36.2) ; U3.7 v1(29.46,51.43) ; U5.H7 v1(57.18,83.92) ; C23.1 v1(79.81,26.03) ; 21.72,84.45 v1(20.07,84.45) ; U5.G1 v1(48.49,85.19) ; U13.24 v1(87,95.71) ; U17.8 v1(110.49,89.08) ; U4.7 v1(32.77,77.47) ; U8.20 v1(74.78,40.64) ; U17.24 v1(111.76,95.71) ; U18.2 v1(89.71,30.48) ; U5.B7 v1(57.18,92.61) ; U11.8 v1(110.49,101.78) ; U21.2 v1(90.35,10.16)
  BOTTOM w0.381: C18.1 v1(74.3,101.85) ; C3.1 v1(28.83,71.88) ; C22.1 v1(74.3,63.75) ; C4.1 v1(46.74,59.69) ; C16.1 v1(99.06,77.09) ; C20.1 v1(74.3,89.79) ; C1.1 v1(28.32,22.23) ; C17.1 v1(99.06,89.79) ; C19.1 v1(99.06,64.39) ; C15.1 v1(99.06,102.49) ; C2.1 v1(28.96,44.45) ; C21.1 v1(74.3,76.45)
A0: length 2.1
  TOP w0.127: U4.47 v1(19.66,74.3)
A1: length 1.7
  TOP w0.127: U4.46 v1(20.07,74.93)
A2: length 1.7
  TOP w0.127: 21.72,76.2 v1(20.07,76.2)
A3: length 2.1
  TOP w0.127: 21.72,76.83 v1(19.66,76.83)
A4: length 2.1
  TOP w0.127: 21.72,78.11 v1(19.66,78.11)
A5: length 1.7
  TOP w0.127: 21.72,78.74 v1(20.07,78.74)
A6: length 1.7
  TOP w0.127: 21.72,80.01 v1(20.07,80.01)
A7: length 2.1
  TOP w0.127: 21.72,80.64 v1(19.66,80.64)
AD0: length 2
  TOP w0.127: U1.47 v1(19.05,26.03)
AD1: length 1.7
  TOP w0.127: U1.46 v1(19.43,26.67)
AD2: length 1.7
  TOP w0.127: U1.44 v1(19.43,27.94)
AD3: length 2
  TOP w0.127: U1.43 v1(19.05,28.58)
AD4: length 2
  TOP w0.127: U1.41 v1(19.05,29.84)
AD5: length 1.7
  TOP w0.127: U1.40 v1(19.43,30.48)
AD6: length 2.2
  TOP w0.127: U1.38 v1(23.24,31.75)
AD7: length 1.7
  TOP w0.127: U1.37 v1(22.73,32.38)
BA0: length 5.7
  TOP w0.127: U4.13 v1(32.77,81.28) ; U1.13 v1(32.13,33.02) ; U5.A6 v1(55.91,93.88) ; U3.13 v1(32.77,55.24)
BA1: length 7
  TOP w0.127: U1.14 v1(32.64,33.66) ; U4.14 v1(33.17,81.91) ; U5.A7 v1(57.18,93.88) ; U3.14 v1(33.15,55.88)
BA2: length 7
  TOP w0.127: U5.A8 v1(58.45,93.88) ; U3.16 v1(33.27,57.15) ; U1.16 v1(32.51,34.92) ; U4.16 v1(33.17,83.19)
BA3: length 5.7
  TOP w0.127: U3.17 v1(32.77,57.78) ; U4.17 v1(32.77,83.82) ; U5.A9 v1(59.72,93.88) ; U1.17 v1(32.13,35.56)
BA4: length 5
  TOP w0.127: U3.19 v1(32.77,59.05) ; U4.19 v1(32.77,85.09) ; U1.19 v1(32.13,36.83)
BA5: length 6.1
  TOP w0.127: U1.20 v1(32.51,37.46) ; U4.20 v1(33.17,85.72) ; U3.20 v1(33.15,59.69)
BA6: length 6.1
  TOP w0.127: 31.11,87 v1(33.17,87) ; U1.22 v1(32.51,38.73) ; U3.22 v1(33.15,60.96)
BA7: length 5
  TOP w0.127: U1.23 v1(32.13,39.37) ; U3.23 v1(32.77,61.59) ; U4.23 v1(32.77,87.63)
BD0: length 2.8
  TOP w0.127: U4.12 v1(33.17,80.64) ; U5.C5 v1(53.57,91.34)
BD1: length 2.4
  TOP w0.127: U4.11 v1(32.77,80.01) ; U5.C4 v1(52.3,91.34)
BD2: length 2.4
  TOP w0.127: U5.C3 v1(51.03,91.34) ; U4.9 v1(32.77,78.74)
BD3: length 2.8
  TOP w0.127: U4.8 v1(33.17,78.11) ; U5.C2 v1(49.76,91.34)
BD4: length 2.8
  TOP w0.127: U5.C1 v1(48.49,91.34) ; U4.6 v1(33.17,76.83)
BD5: length 2.4
  TOP w0.127: U4.5 v1(32.77,76.2) ; U5.B10 v1(60.99,92.61)
BD6: length 2.4
  TOP w0.127: U4.3 v1(32.77,74.93) ; U5.B9 v1(59.72,92.61)
BD7: length 2.8
  TOP w0.127: U4.2 v1(33.17,74.3) ; U5.B8 v1(58.45,92.61)
BD8: length 4.2
  TOP w0.127: U1.12 v1(32.64,32.38) ; U3.2 v1(33.15,48.26)
BD9: length 3.3
  TOP w0.127: U1.11 v1(32.13,31.75) ; U3.3 v1(32.77,48.89)
BD10: length 3.3
  TOP w0.127: U3.5 v1(32.77,50.16) ; U1.9 v1(32.13,30.48)
BD11: length 4.2
  TOP w0.127: U3.6 v1(33.15,50.8) ; U1.8 v1(32.64,29.84)
BD12: length 4.1
  TOP w0.127: U1.6 v1(32.51,28.58) ; U3.8 v1(33.17,52.07)
BD13: length 3.3
  TOP w0.127: U1.5 v1(32.13,27.94) ; U3.9 v1(32.77,52.7)
BD14: length 3.3
  TOP w0.127: U1.3 v1(32.13,26.67) ; U3.11 v1(32.77,53.98)
BD15: length 4.1
  TOP w0.127: U1.2 v1(32.51,26.03) ; U3.12 v1(33.15,54.61)
BNC2: length 14.4
  BOTTOM w0.127: C5.1 v1(120.5,39.37) 120.27,39.14 120.27,33.91 J2.1 115.57,33.02 L1.2
BNC3: length 13.4
  BOTTOM w0.127: L2.2 116.84,13.97 J3.1 120.27,14.86 120.27,19.46 v1(120.5,19.69) C6.1
BRD: length 0.8
  TOP w0.127: U5.D9 v1(59.72,90.07)
BRESET: length 0.8
  TOP w0.127: U5.B2 v1(49.76,92.61)
BWR: length 0.8
  TOP w0.127: U5.H2 v1(49.76,83.92)
D0: length 49.4
  TOP w0.127: 21.72,61.59 v1(20.07,61.59)
  TOP w0.254: v1(23.37,87.63) v1(16.76,87.63)
  INNER_1 w0.127: v1(23.37,87.63) 26.92,84.07 26.92,69.85 19.68,62.61 19.68,61.98 v1(20.07,61.59) ; J1.28 8.64,85.34 13.84,85.34 16.13,87.63 v1(16.76,87.63)
D1: length 51.6
  TOP w0.127: v1(19.68,60.96) 21.72,60.96
  TOP w0.254: 21.72,87 v1(19.68,87)
  INNER_1 w0.127: v1(19.68,60.96) 19.43,61.21 19.43,62.74 26.67,69.98 26.67,83.57 23.24,87 v1(19.68,87) 16.13,87 14.1,84.96 8.76,84.96 J1.27
D2: length 51.9
  TOP w0.254: 21.72,59.69 v1(20.07,59.69) ; 21.72,85.72 v1(19.68,85.72)
  INNER_1 w0.127: J1.26 9.14,82.8 13.59,82.8 16.51,85.72 v1(19.68,85.72) 23.24,85.72 26.42,82.55 26.42,70.1 19.18,62.86 19.18,60.58 v1(20.07,59.69)
D3: length 54.3
  TOP w0.254: 21.72,85.09 v1(19.18,85.09) ; v1(19.68,59.05) 21.72,59.05
  INNER_1 w0.127: J1.25 9.02,80.14 9.02,81.66 9.91,82.55 13.84,82.55 16.38,85.09 v1(19.18,85.09) 23.24,85.09 26.16,82.17 26.16,70.23 18.92,62.99 18.92,59.82 v1(19.68,59.05)
D4: length 55.2
  TOP w0.254: 21.72,83.82 v1(19.68,83.82) ; v1(20.07,57.78) 21.72,57.78
  INNER_1 w0.127: J1.24 9.52,78.11 9.52,81.53 10.29,82.3 14.22,82.3 15.75,83.82 v1(19.68,83.82) 23.22,83.82 25.91,81.13 25.91,70.36 18.67,63.12 18.67,59.18 v1(20.07,57.78)
D5: length 56.3
  TOP w0.254: v1(19.68,57.15) 21.72,57.15 ; 21.72,83.19 v1(19.3,83.19)
  INNER_1 w0.127: v1(19.68,57.15) 18.41,58.42 18.41,63.25 25.65,70.48 25.65,80.77 23.24,83.19 v1(19.3,83.19) 16.64,83.19 13.72,80.26 11.3,80.26 10.03,78.99 10.03,76.07 J1.23
D6: length 57.4
  TOP w0.254: 21.72,81.91 v1(19.56,81.91) ; v1(20.07,55.88) 21.72,55.88
  INNER_1 w0.127: v1(20.07,55.88) 18.16,57.78 18.16,63.37 25.4,70.61 25.4,79.76 23.24,81.91 v1(19.56,81.91) 16,81.91 14.1,80.01 11.68,80.01 10.41,78.74 10.41,73.91 J1.22
D7: length 59.8
  TOP w0.254: v1(19.68,55.24) 21.72,55.24 ; 21.72,81.28 v1(19.18,81.28)
  INNER_1 w0.127: J1.21 10.79,71.75 10.79,78.23 12.32,79.76 14.35,79.76 15.87,81.28 v1(19.18,81.28) 23.24,81.28 25.15,79.38 25.15,70.74 17.91,63.5 17.91,57.02 v1(19.68,55.24)
DATA: length 0.8
  TOP w0.127: U5.B4 v1(52.3,92.61)
DCLK: length 0.8
  TOP w0.203: U5.A10 v1(60.99,93.88)
DDIR: length 3.3
  TOP w0.127: U1.48 v1(19.43,25.4) ; U4.48 v1(20.07,73.66)
DEN: length 3.3
  TOP w0.127: U4.1 v1(32.77,73.66) ; U1.1 v1(32.13,25.4)
DHEN: length 1.7
  TOP w0.127: U3.1 v1(32.77,47.62)
FPGA: length 0.8
  TOP w0.127: U5.C10 v1(60.99,91.34)
GAIN: length 24.2
  TOP w0.127: U5.C8 v1(58.45,91.34) ; U23.6 v1(96.44,19.05) ; U19.6 v1(96.44,38.73)
  BOTTOM w0.127: v1(96.44,38.73) 95.38,37.67 95.38,20.17 96.44,19.1 v1(96.44,19.05)
HS: length 0.8
  TOP w0.127: U5.C9 v1(59.72,91.34)
MCLK: length 0.8
  TOP w0.203: U5.J1 v1(48.49,82.65)
N00036_DATA_DAAMP: length 33.3
  TOP w0.127: U18.8 v1(89.92,38.1) 94.54,38.1 96.44,40 U19.5 v1(99.44,40) ; U18.5 v1(89.92,34.29)
  BOTTOM w0.127: L4.2 104.14,27.94 R15.1 R16.1 101.6,36.32 99.44,38.48 v1(99.44,40) ; v1(89.92,38.1) v1(89.92,34.29)
N00036_DATA_DAAMP0: length 33
  TOP w0.127: U21.8 v1(90.35,17.78) 93.7,17.78 96.24,20.32 U23.5 v1(99.34,20.32) ; U21.5 v1(90.35,13.97)
  BOTTOM w0.127: v1(90.35,13.97) v1(90.35,17.78) ; L6.2 104.78,8.25 R18.1 R17.1 101.6,16.38 99.34,18.64 v1(99.34,20.32)
N00038_DATA_DAAMP: length 27.7
  TOP w0.127: v1(83.82,31.55) 85.29,33.02 U18.4 89.81,33.02 96.8,26.03 104.78,26.03 L3.2
  BOTTOM w0.127: C24.1 v1(83.82,31.55)
N00038_DATA_DAAMP0: length 27.5
  TOP w0.127: v1(84.45,11.23) 85.93,12.7 U21.4 90.35,12.7 96.57,6.48 105.28,6.48 L5.2
  BOTTOM w0.127: C27.1 v1(84.45,11.23)
N00044_DATA_DAAMP: length 41.1
  TOP w0.127: U19.1 v1(104.32,36.2)
  BOTTOM w0.127: v1(104.32,36.2) 105.54,37.41 105.54,38.73 107.42,40.61 112.42,40.61 114.05,38.99 114.05,33.66 112.78,32.38 112.78,23.75 114.68,21.84 114.68,16.51 113.51,15.34 U20.2
N00044_DATA_DAAMP0: length 24.1
  TOP w0.127: U23.1 104.32,16.51 109.27,21.46 v1(111.12,21.46)
  BOTTOM w0.127: U22.2 111.66,22.76 111.12,22.23 v1(111.12,21.46)
N00060_DATA_DAAMP: length 52.9
  TOP w0.127: v1(105.03,35.56) U18.6
  BOTTOM w0.127: v1(105.03,35.56) 105.79,36.32 105.79,38.61 107.54,40.36 112.29,40.36 113.66,38.99 113.66,33.78 112.4,32.51 112.4,23.37 114.17,21.59 114.17,18.29 U20.3
N00060_DATA_DAAMP0: length 45.6
  TOP w0.127: U21.6 v1(92.96,15.24) ; v1(112.01,22.23) v1(92.96,22.23)
  BOTTOM w0.127: v1(92.96,22.23) v1(92.96,15.24) ; U22.3 113.28,35.94 113.28,34.16 112.01,32.89 v1(112.01,22.23)
N282866_DATA_DAAMP: length 4.8
  TOP w0.127: U19.8 v1(99.34,36.2)
  BOTTOM w0.127: R16.2 99.31,36.17 v1(99.34,36.2) 99.19,36.2
N282866_DATA_DAAMP0: length 4
  TOP w0.127: U23.8 v1(99.34,16.51)
  BOTTOM w0.127: R17.2 99.31,16.48 v1(99.34,16.51)
N282912_DATA_DAAMP: length 15
  TOP w0.127: U19.2 100.58,37.46 99.95,36.83 v1(96.39,36.83)
  BOTTOM w0.127: R15.2 98.2,30.48 96.39,32.28 v1(96.39,36.83)
N282912_DATA_DAAMP0: length 14.3
  TOP w0.127: U23.2 101.6,17.78 101.04,17.22 v1(96.47,17.22)
  BOTTOM w0.127: v1(96.47,17.22) 96.47,13.13 98.17,11.43 R18.2
NCS: length 0.8
  TOP w0.127: U5.B1 v1(48.49,92.61)
OE: length 0.8
  TOP w0.127: U5.J2 v1(49.76,82.65)
OUTA: length 13.3
  BOTTOM w0.127: L1.1 108.69,28.47 U20.6
OUTB: length 30.5
  BOTTOM w0.127: L2.1 106.68,14.99 106.17,15.49 106.17,22.1 107.06,22.99 107.06,28.47 105.18,30.35 105.18,33.3 106.04,34.16 106.04,37.87 106.78,38.61 108.03,38.61 U22.6
Q0: length 7.3
  TOP w0.127: U6.12 R4.1
Q1: length 32
  TOP w0.127: R4.2 D4.2
Q2: length 7.3
  TOP w0.127: U6.14 R3.1
Q3: length 25
  TOP w0.127: R3.2 D3.2
Q4: length 7.3
  TOP w0.127: U6.16 R2.1
Q5: length 18
  TOP w0.127: R2.2 D2.2
Q6: length 7.3
  TOP w0.127: U6.18 R1.1
Q7: length 10.4
  TOP w0.127: R1.2 D1.2
RA0: length 133.1
  TOP w0.127: U11.5 106.68,98.88 107.19,98.37 107.19,92.66 106.68,92.15 U17.5 106.68,86.18 107.19,85.67 v1(107.19,79.96) 106.68,79.45 U16.5 106.68,73.48 107.31,72.85 107.31,67.28 106.68,66.65 U12.5 ; U10.5 81.91,66.65 82.55,67.28 82.55,72.85 81.91,73.48 U14.5 v1(81.91,79.5) 81.97,79.5 82.42,79.96 82.42,85.67 81.91,86.18 U13.5 81.91,92.15 82.42,92.66 82.42,98.37 81.91,98.88 U15.5 ; U5.H6 v1(55.91,83.92)
  BOTTOM w0.127: v1(55.91,83.92) 56.41,83.41 62.89,83.41 66.67,79.63 80.77,79.63 80.9,79.5 v1(81.91,79.5) 82.42,79.5 82.83,79.91 104.62,79.91 104.78,79.76 106.98,79.76 v1(107.19,79.96)
RA1: length 129.4
  TOP w0.127: U11.4 105.41,98.88 105.92,98.37 105.92,92.66 105.41,92.15 U17.4 105.41,86.18 105.89,85.7 105.89,85.57 105.92,85.55 105.92,83.36 105.89,83.34 v1(105.89,80.26) 105.89,79.93 105.41,79.45 U16.4 105.41,73.48 106.04,72.85 106.04,67.28 105.41,66.65 U12.4 ; 80.64,62.23 80.64,66.65 81.28,67.28 81.28,72.85 80.64,73.48 80.64,79.35 81.15,79.86 v1(81.15,80.26) 81.15,85.67 80.64,86.18 80.64,92.15 81.15,92.66 81.15,98.37 80.64,98.88 80.64,100.33 ; U5.H8 v1(58.45,83.92)
  BOTTOM w0.127: v1(58.45,83.92) 58.95,84.43 62.26,84.43 66.8,79.88 80.77,79.88 v1(81.15,80.26) v1(105.89,80.26)
RA2: length 129
  TOP w0.127: U15.3 79.38,98.88 79.88,98.37 79.88,92.66 79.38,92.15 v1(79.38,91.95) U13.3 79.38,86.18 79.88,85.67 79.88,79.96 79.38,79.45 U14.3 79.38,73.48 80.01,72.85 80.01,67.28 79.38,66.65 U10.3 ; U5.H9 v1(59.72,83.92) ; U12.3 104.14,66.65 104.78,67.28 104.78,72.85 104.14,73.48 U16.3 104.14,79.45 104.65,79.96 104.65,85.67 104.14,86.18 U17.3 104.14,92.15 104.65,92.66 v1(104.65,92.84) 104.65,98.37 104.14,98.88 U11.3
  INNER_2 w0.127: v1(59.72,83.92) 60.22,83.41 70.84,83.41 v1(79.38,91.95)
  BOTTOM w0.127: v1(104.65,92.84) 103.17,92.84 102.9,93.12 80.54,93.12 v1(79.38,91.95)
RA3: length 126.6
  TOP w0.127: 78.1,100.33 78.1,98.88 78.61,98.37 v1(78.61,92.71) 78.61,92.66 78.1,92.15 78.1,86.18 78.61,85.67 78.61,79.96 78.1,79.45 78.1,73.48 78.74,72.85 78.74,67.28 78.1,66.65 78.1,62.23 ; U11.2 102.87,98.88 103.38,98.37 v1(103.38,93.34) 103.38,92.74 102.87,92.23 U17.2 102.87,86.18 103.38,85.67 103.38,79.96 102.87,79.45 U16.2 102.87,73.48 103.5,72.85 103.5,67.28 102.87,66.65 U12.2 ; U5.H10 v1(60.99,83.92)
  INNER_2 w0.127: v1(60.99,83.92) 61.01,83.95 70.87,83.95 78.61,91.69 v1(78.61,92.71)
  BOTTOM w0.127: v1(78.61,92.71) 79.27,93.37 103.1,93.37 103.12,93.34 v1(103.38,93.34)
RA4: length 123.9
  TOP w0.127: U11.32 101.6,105.41 v1(101.35,105.16) 101.09,104.9 101.09,98.88 101.6,98.37 U17.32 101.6,92.71 101.09,92.2 101.09,86.18 101.6,85.67 U16.32 101.6,79.96 102.11,79.45 102.11,73.63 101.6,73.13 U12.32 ; U10.32 76.84,73.13 77.34,73.63 77.34,79.45 76.84,79.96 U14.32 v1(76.84,85.9) 76.78,85.9 76.33,86.36 76.33,92.2 76.84,92.71 U13.32 76.84,98.37 76.33,98.88 v1(76.33,104.01) 76.33,104.9 76.84,105.41 U15.32 ; U5.G8 v1(58.45,85.19)
  INNER_1 w0.127: v1(58.45,85.19) 59.16,85.9 v1(76.84,85.9)
  BOTTOM w0.127: v1(101.35,105.16) 101.09,105.41 83.19,105.41 81.79,104.01 v1(76.33,104.01)
RA5: length 124.6
  TOP w0.127: U12.31 102.87,72.97 102.36,73.48 102.36,79.5 102.87,80.01 U16.31 102.87,85.67 102.36,86.18 102.36,92.43 102.87,92.94 U17.31 102.87,98.37 102.36,98.88 102.36,104.93 v1(102.79,105.36) 102.87,105.44 U11.31 ; 78.1,109.86 78.1,105.44 77.6,104.93 v1(77.6,104.52) 77.6,98.88 78.1,98.37 78.1,92.86 77.6,92.35 77.6,86.18 78.1,85.67 v1(78.1,82.93) 78.1,80.01 77.6,79.5 77.6,73.48 78.1,72.97 78.1,71.75 ; U5.G9 v1(59.72,85.19)
  BOTTOM w0.127: v1(59.72,85.19) 60.22,84.68 63.02,84.68 64.77,82.93 v1(78.1,82.93) ; v1(77.6,104.52) 81.91,104.52 83.06,105.66 102.49,105.66 v1(102.79,105.36)
RA6: length 124.3
  TOP w0.127: U11.30 v1(104.14,105.66) 104.14,105.41 103.63,104.9 103.63,98.86 104.11,98.37 104.14,98.37 U17.30 104.14,92.71 103.63,92.2 103.63,86.16 104.11,85.67 104.14,85.67 U16.30 104.14,80.01 103.63,79.5 103.63,73.48 104.14,72.97 U12.30 ; U10.30 79.38,73 78.87,73.51 78.87,79.5 79.38,80.01 v1(79.38,82.93) U14.30 79.38,85.67 79.35,85.67 78.87,86.16 78.87,92.2 79.38,92.71 U13.30 79.38,98.37 79.35,98.37 78.87,98.86 78.87,104.9 v1(79.12,105.16) 79.38,105.41 U15.30 ; U5.G10 v1(60.99,85.19)
  BOTTOM w0.127: v1(79.38,82.93) 78.74,83.57 64.9,83.57 63.25,85.22 61.01,85.22 v1(60.99,85.19) ; v1(79.12,105.16) 82.17,105.16 82.93,105.92 103.89,105.92 v1(104.14,105.66)
RA7: length 128.7
  TOP w0.127: U12.29 105.41,72.97 104.9,73.48 104.9,79.5 105.38,79.98 105.38,84.43 U16.29 105.41,85.67 105.38,85.67 104.9,86.16 v1(104.9,91.31) 104.9,92.2 105.41,92.71 U17.29 105.41,98.37 105.38,98.37 104.9,98.86 104.9,104.9 105.41,105.41 U11.29 ; 80.64,71.75 80.64,72.97 80.14,73.48 80.14,79.5 80.64,80.01 80.64,85.67 80.62,85.67 80.14,86.16 v1(80.14,89.92) 80.14,92.2 80.64,92.71 80.64,98.37 80.62,98.37 80.14,98.86 80.14,104.9 80.64,105.41 80.64,109.86 ; 57.91,87 v1(58.45,86.46)
  INNER_1 w0.127: v1(58.45,86.46) 59.74,87.76 77.98,87.76 v1(80.14,89.92)
  BOTTOM w0.127: v1(104.9,91.31) 103.12,91.31 102.34,92.1 91.21,92.1 89.66,90.55 83.92,90.55 83.29,89.92 v1(80.14,89.92)
RA8: length 128.2
  TOP w0.127: U12.28 106.68,73 106.17,73.51 106.17,79.5 106.68,80.01 U16.28 106.68,85.67 106.65,85.67 106.17,86.16 106.17,92.2 106.68,92.71 U17.28 106.68,98.37 106.65,98.37 106.17,98.86 106.17,104.85 106.68,105.36 v1(106.68,106.17) U11.28 ; 59.18,87 v1(59.72,86.46) ; U15.28 v1(81.91,105.66) 81.91,105.36 81.41,104.85 81.41,98.86 81.89,98.37 81.91,98.37 U13.28 81.91,92.71 81.41,92.2 81.41,86.16 81.89,85.67 81.91,85.67 U14.28 v1(81.91,82.8) 81.91,80.21 81.41,79.71 81.41,73.48 81.91,72.97 U10.28
  BOTTOM w0.127: v1(106.68,106.17) 82.42,106.17 v1(81.91,105.66) ; v1(81.91,82.8) 80.77,83.95 65.28,83.95 63.37,85.85 60.32,85.85 v1(59.72,86.46)
RA9: length 138.2
  TOP w0.127: U5.E8 v1(58.45,88.8) ; U15.22 89.53,105.36 89.08,104.9 v1(89.03,104.9) 89.03,98.88 89.53,98.37 U13.22 89.53,92.86 89.03,92.35 89.03,86.18 89.53,85.67 U14.22 v1(89.53,82.93) 89.53,80.01 89.03,79.5 89.03,73.48 89.53,72.97 U10.22 ; U11.22 114.3,105.36 113.79,104.85 v1(113.79,104.77) 113.79,98.88 114.3,98.37 U17.22 114.3,92.71 113.79,92.2 113.79,86.16 114.27,85.67 114.3,85.67 U16.22 114.3,80.01 113.79,79.5 113.79,73.48 114.3,72.97 U12.22
  BOTTOM w0.127: v1(89.53,82.93) 88.01,84.45 65.15,84.45 62.1,87.5 59.74,87.5 v1(58.45,88.8) ; v1(89.03,104.9) 89.28,105.16 100.61,105.16 101.12,104.65 113.66,104.65 v1(113.79,104.77)
RA10: length 138
  TOP w0.127: U15.21 90.81,105.36 91.31,104.85 v1(91.31,104.65) 91.31,98.88 90.81,98.37 U13.21 90.81,92.66 91.31,92.15 91.31,86.18 90.81,85.67 U14.21 v1(90.81,82.8) 90.81,79.96 91.31,79.45 91.31,73.48 90.81,72.97 U10.21 ; U12.21 115.57,72.97 116.08,73.48 116.08,79.45 115.57,79.96 U16.21 115.57,85.67 116.08,86.18 116.08,92.15 115.57,92.66 U17.21 115.57,98.37 116.08,98.88 v1(116.08,104.27) 116.08,104.85 115.57,105.36 U11.21 ; U5.E9 v1(59.72,88.8)
  BOTTOM w0.127: v1(91.31,104.65) 100.74,104.65 101.12,104.27 v1(116.08,104.27) ; v1(59.72,88.8) 60.76,87.76 62.36,87.76 65.41,84.71 88.9,84.71 v1(90.81,82.8)
RA11: length 140.1
  TOP w0.127: U15.20 92.07,105.41 92.58,104.9 92.58,98.88 92.07,98.37 U13.20 v1(92.07,95.5) 92.07,92.71 92.58,92.2 92.58,86.18 92.07,85.67 U14.20 92.07,79.96 92.58,79.45 92.58,73.48 92.07,72.97 U10.20 ; U11.20 116.84,105.41 117.35,104.9 117.35,98.88 116.84,98.37 U17.20 v1(116.84,95) 116.84,92.71 117.35,92.2 117.35,86.18 116.84,85.67 U16.20 116.84,79.96 117.35,79.45 117.35,73.48 116.84,72.97 U12.20 ; U5.E10 v1(61.19,88.27)
  INNER_2 w0.127: v1(61.19,88.27) 74.78,88.27 78.1,91.59 78.1,92.91 78.41,93.22 89.79,93.22 v1(92.07,95.5)
  BOTTOM w0.127: v1(116.84,95) 116.59,94.74 107.82,94.74 106.15,96.42 92.99,96.42 v1(92.07,95.5)
RA12: length 158.5
  TOP w0.127: 93.34,71.75 93.34,73.08 92.84,73.58 92.84,79.5 93.34,80.01 93.34,85.78 92.84,86.28 92.84,92.2 93.34,92.71 v1(93.34,95.25) 93.34,98.48 92.84,98.98 92.84,104.85 93.34,105.36 93.34,109.86 ; U11.19 118.11,105.36 117.6,104.85 117.6,98.98 118.11,98.48 U17.19 v1(118.11,94.49) 118.11,92.71 117.6,92.2 117.6,86.28 118.11,85.78 U16.19 118.11,80.01 117.6,79.5 117.6,73.58 118.11,73.08 U12.19 ; U5.G2 v1(49.76,85.19)
  INNER_1 w0.127: v1(93.34,95.25) 92.74,94.64 50.7,94.64 50.27,94.21 50.27,87.76 49.25,86.74 49.25,85.7 v1(49.76,85.19)
  BOTTOM w0.127: v1(93.34,95.25) 94.26,96.16 106.02,96.16 107.7,94.49 v1(118.11,94.49)
RA13: length 159
  TOP w0.127: U12.18 119.38,73 118.87,73.51 118.87,79.5 119.38,80.01 U16.18 119.38,85.67 119.35,85.67 118.87,86.16 118.87,92.2 119.38,92.71 v1(119.38,93.98) U17.18 119.38,98.37 119.35,98.37 118.87,98.86 118.87,104.85 119.38,105.36 U11.18 ; U15.18 94.62,105.36 94.11,104.85 94.11,98.86 94.59,98.37 94.62,98.37 U13.18 v1(94.62,95.25) 94.62,92.71 94.11,92.2 94.11,86.16 94.59,85.67 94.62,85.67 U14.18 94.62,80.01 94.11,79.5 94.11,73.48 94.62,72.97 U10.18 ; 50.29,87 v1(49.76,86.46)
  INNER_1 w0.127: v1(94.62,95.25) 92.76,93.37 52.1,93.37 51.79,93.68 51.79,94.11 51.51,94.39 50.83,94.39 50.52,94.08 50.52,87.22 v1(49.76,86.46)
  BOTTOM w0.127: v1(94.62,95.25) 95.28,95.91 105.77,95.91 107.7,93.98 v1(119.38,93.98)
RA14: length 156.7
  TOP w0.127: U5.E2 v1(49.76,88.8) ; U10.15 94.62,66.65 95.25,67.28 95.25,72.85 94.62,73.48 U14.15 v1(94.62,78.61) 94.62,79.45 95.12,79.96 95.12,85.67 94.62,86.18 U13.15 94.62,92.15 95.12,92.66 95.12,98.37 94.62,98.88 U15.15 ; U11.15 119.38,98.88 119.89,98.37 119.89,92.66 119.38,92.15 U17.15 119.38,86.18 119.89,85.67 119.89,79.96 119.38,79.45 v1(119.38,77.85) U16.15 119.38,73.48 120.01,72.85 120.01,67.28 119.38,66.65 U12.15
  INNER_2 w0.127: v1(49.76,88.8) 49.25,88.29 49.25,86.26 49.56,85.95 49.91,85.95 50.52,85.34 51.59,85.34 56.41,80.52 78.23,80.52 80.7,78.05 94.06,78.05 v1(94.62,78.61)
  BOTTOM w0.127: v1(94.62,78.61) 94.89,78.89 104.11,78.89 105.16,77.85 v1(119.38,77.85)
RA15: length 155.5
  TOP w0.127: U11.14 118.11,98.88 118.62,98.37 118.62,92.66 118.11,92.15 U17.14 118.11,86.18 118.62,85.67 118.62,79.96 118.11,79.45 v1(118.11,78.36) U16.14 118.11,73.48 118.75,72.85 118.75,67.28 118.11,66.65 U12.14 ; U5.D2 v1(49.76,90.07) ; 93.34,62.23 93.34,66.65 93.98,67.28 93.98,72.85 93.34,73.48 v1(93.34,78.87) 93.34,79.45 93.85,79.96 93.85,85.67 93.34,86.18 93.34,92.15 93.85,92.66 93.85,98.37 93.34,98.88 93.34,100.33
  INNER_2 w0.127: v1(49.76,90.07) 50.01,89.81 50.27,89.53 50.27,86.13 50.8,85.6 51.84,85.6 56.67,80.77 78.36,80.77 80.77,78.36 92.84,78.36 v1(93.34,78.87)
  BOTTOM w0.127: v1(93.34,78.87) 93.62,79.15 104.24,79.15 105.03,78.36 v1(118.11,78.36)
RCS0: length 42.7
  TOP w0.127: 83.19,62.23 83.19,66.65 83.82,67.28 83.82,72.85 83.19,73.48 v1(83.19,76.33) ; U5.J8 v1(58.45,82.65)
  BOTTOM w0.127: v1(83.19,76.33) 81.66,76.33 79.25,78.74 62.36,78.74 v1(58.45,82.65)
RCS1: length 63
  TOP w0.127: U11.6 v1(107.95,98.81) ; U5.J9 v1(59.72,82.65) ; 83.19,100.33 v1(83.19,98.81)
  INNER_2 w0.127: v1(59.72,82.65) 59.21,83.16 59.21,87.02 60.96,88.77 74.9,88.77 77.47,91.34 77.47,93.09 v1(83.19,98.81)
  BOTTOM w0.127: v1(107.95,98.81) v1(83.19,98.81)
RCS2: length 65
  TOP w0.127: v1(107.95,76.45) U16.6 107.95,73.48 108.59,72.85 108.59,67.28 107.95,66.65 U12.6 ; U5.J10 v1(60.99,82.65)
  BOTTOM w0.127: v1(60.99,82.65) 64.39,79.25 66.29,79.25 66.42,79.12 79.25,79.12 80.52,77.85 86.23,77.85 87.63,76.45 v1(107.95,76.45)
RCS3: length 71.2
  TOP w0.127: v1(83.19,91.06) 83.19,87.63 ; 51.56,87 v1(51.03,86.46) ; U17.6 v1(107.95,91.31)
  INNER_2 w0.127: v1(51.03,86.46) 51.84,86.46 56.16,82.14 70.84,82.14 75.56,86.87 78.99,86.87 v1(83.19,91.06)
  BOTTOM w0.127: v1(107.95,91.31) 105.66,91.31 105.16,91.82 103,91.82 102.46,92.35 91.08,92.35 90.3,91.57 83.69,91.57 v1(83.19,91.06)
RD0: length 109.8
  TOP w0.127: U15.26 84.45,105.54 85.09,104.9 85.09,93.12 83.95,91.97 v1(83.95,89.79) 83.95,86.23 84.45,85.72 U14.26 ; 49.02,87 v1(48.49,86.46) ; U17.26 109.22,92.66 108.71,92.15 v1(108.71,91.31) 108.71,86.18 109.22,85.67 U16.26
  BOTTOM w0.127: v1(48.49,86.46) 47.62,87.33 47.62,91.57 48.16,92.1 75.16,92.1 77.85,89.41 83.44,89.41 83.82,89.79 v1(83.95,89.79) 84.45,90.3 89.79,90.3 91.34,91.85 102.21,91.85 103.25,90.8 108.2,90.8 v1(108.71,91.31)
RD1: length 110.8
  TOP w0.127: U17.23 113.03,92.66 112.52,92.15 v1(112.52,91.31) 112.52,86.18 113.03,85.67 U16.23 ; U14.23 88.27,85.72 87.76,86.23 v1(87.76,89.79) 87.76,91.57 89.03,92.84 89.03,98.37 88.77,98.63 88.77,102.92 88.27,103.43 U15.23 ; U5.E1 v1(48.49,88.8)
  BOTTOM w0.127: v1(112.52,91.31) 109.6,91.31 108.84,90.55 103.12,90.55 102.08,91.59 91.47,91.59 89.66,89.79 v1(87.76,89.79) 84.66,89.79 84.02,89.15 77.72,89.15 75.03,91.85 48.29,91.85 47.98,91.54 47.98,89.31 v1(48.49,88.8)
RD2: length 113
  TOP w0.127: U15.10 88.27,98.76 88.77,98.25 88.77,92.96 87.25,91.44 87.25,89.53 87.5,89.28 87.5,83.31 88.27,82.55 v1(88.27,79.12) U14.10 ; U17.10 113.03,86.18 113.54,85.67 113.54,79.96 113.03,79.45 v1(113.03,78.87) U16.10 ; U5.D1 v1(48.49,90.07)
  INNER_2 w0.127: v1(48.49,90.07) 49,90.58 50.01,90.58 50.52,90.07 50.52,86.26 50.93,85.85 51.97,85.85 55.93,81.89 61.52,81.89 62.38,81.03 78.49,81.03 80.9,78.61 87.76,78.61 v1(88.27,79.12)
  BOTTOM w0.127: v1(113.03,78.87) 104.9,78.87 104.37,79.4 88.54,79.4 v1(88.27,79.12)
RD3: length 104.5
  TOP w0.127: U17.7 109.22,86.18 109.73,85.67 109.73,79.96 109.22,79.45 v1(109.22,79.38) U16.7 ; U5.H1 v1(48.49,83.92) ; U14.7 v1(84.45,79.25) 83.69,80.01 83.69,85.72 83.19,86.23 82.98,86.23 82.68,86.54 82.68,91.82 83.82,92.96 83.82,98.3 84.45,98.93 U15.7
  BOTTOM w0.127: v1(109.22,79.38) 104.78,79.38 104.5,79.65 84.86,79.65 v1(84.45,79.25) 82.68,79.25 82.42,78.99 80.9,78.99 80.52,79.38 66.55,79.38 62.76,83.16 55.65,83.16 54.36,84.45 U5.H1 v1(48.49,83.92)
RD4: length 135.5
  TOP w0.127: v1(109.22,68.45) U12.26 109.22,73.02 109.98,73.79 109.98,104.52 109.22,105.28 U11.26 ; U13.26 v1(84.45,95.71) 84.45,92.96 83.69,92.2 83.69,90.86 83.44,90.6 83.44,89.59 83.69,89.33 83.69,86.11 83.95,85.85 83.95,80.67 84.96,79.65 84.96,73.79 84.45,73.28 U10.26 v1(84.45,68.33) ; U5.A1 v1(48.49,93.88)
  BOTTOM w0.127: v1(109.22,68.45) 108.76,68 89.1,68 88.77,68.33 v1(84.45,68.33) ; v1(84.45,95.71) 82.42,93.68 79.04,93.68 78.84,93.47 62.46,93.47 61.44,94.49 49.1,94.49 v1(48.49,93.88)
RD5: length 140.1
  TOP w0.127: U13.23 v1(88.27,95.71) 88.27,92.84 86.49,91.06 86.49,80.04 87.63,78.89 87.63,73.66 88.27,73.02 U10.23 88.27,67.74 v1(88.24,67.72) ; U12.23 v1(113.03,67.92) ; v1(112.42,95.25) 112.42,104.67 113.03,105.28 U11.23 ; U5.A2 v1(49.76,93.88)
  INNER_1 w0.127: v1(49.76,93.88) 49.76,94.36 50.29,94.89 87.4,94.89 88.21,95.71 v1(88.27,95.71)
  BOTTOM w0.127: v1(112.42,95.25) 112.29,95.25 112.24,95.2 107.75,95.2 106.17,96.77 89.33,96.77 v1(88.27,95.71) ; v1(88.24,67.72) 112.83,67.72 v1(113.03,67.92)
RD6: length 135.6
  TOP w0.127: U12.10 v1(113.03,67.18) ; U10.10 88.27,66.7 88.75,67.18 v1(88.77,67.18) 88.77,85.6 88.27,86.11 U13.10 v1(88.27,89.03) ; v1(113.03,89.66) 113.03,92.2 113.54,92.71 113.54,98.42 113.03,98.93 U11.10 ; U5.A3 v1(51.03,93.88)
  INNER_1 w0.127: v1(88.27,89.03) 87.76,88.52 82.93,88.52 81.03,90.42 79.76,90.42 78.61,89.28 74.09,89.28 74.07,89.31 52.81,89.31 51.56,90.55 U5.A3 v1(51.03,93.88)
  BOTTOM w0.127: v1(88.27,89.03) 109.47,89.03 110.11,89.66 v1(113.03,89.66) ; v1(88.77,67.18) v1(113.03,67.18)
RD7: length 127.4
  TOP w0.127: v1(85.34,92.58) 84.45,91.69 U13.7 84.45,86.11 85.22,85.34 85.22,67.31 v1(84.45,66.55) U10.7 ; U5.A4 v1(52.3,93.88) ; U11.7 109.22,98.81 108.71,98.3 108.71,92.71 108.33,92.33 v1(108.2,92.33) ; U12.7 v1(109.22,66.55)
  BOTTOM w0.127: v1(84.45,66.55) v1(109.22,66.55) ; v1(108.2,92.33) 103.25,92.33 102.72,92.86 85.62,92.86 v1(85.34,92.58) 80.9,92.58 79.76,91.44 77.85,91.44 76.17,93.12 53.06,93.12 v1(52.3,93.88)
RESET: length 0.8
  TOP w0.127: U5.B5 v1(53.57,92.61)
RWE: length 143.2
  TOP w0.127: U15.11 89.53,98.88 90.04,98.37 90.04,92.66 v1(89.74,92.35) 89.53,92.15 U13.11 89.53,86.18 90.04,85.67 90.04,79.96 89.53,79.45 U14.11 89.53,73.48 90.17,72.85 90.17,67.28 89.53,66.65 U10.11 ; U11.11 114.3,98.88 114.81,98.37 114.81,92.66 114.3,92.15 v1(114.3,91.82) U17.11 114.3,86.18 114.81,85.67 114.81,79.96 114.3,79.45 U16.11 114.3,73.48 114.94,72.85 114.94,67.28 114.3,66.65 U12.11 ; v1(54.64,84.99) U5.H5
  INNER_2 w0.127: v1(76.84,91.44) 74.42,89.03 60.71,89.03 58.65,86.97 56.62,86.97 v1(54.64,84.99)
  BOTTOM w0.127: v1(114.3,91.82) 105.79,91.82 105.54,92.08 103.12,92.08 102.59,92.61 90.96,92.61 90.91,92.56 89.94,92.56 v1(89.74,92.35) 89.46,92.08 80.9,92.08 79.88,91.06 77.22,91.06 v1(76.84,91.44)
SEL: length 0.8
  TOP w0.127: U5.B3 v1(51.03,92.61)
V+12: length 4.9
  TOP w0.381: U19.4 v1(104.32,40) ; U23.4 v1(104.32,20.32)
  BOTTOM w0.381: C25.1 v1(102.62,27.3) ; C28.1 v1(102.62,8.25)
VCLKA: length 28
  TOP w0.203: U5.J4 v1(52.3,82.65) ; U18.11 v1(77.62,40.64) ; U21.11 v1(78.26,20.32) ; U8.11 v1(74.78,29.21)
  BOTTOM w0.127: v1(77.62,40.64) 74.78,37.8 v1(74.78,29.21) 78.26,25.73 v1(78.26,20.32)
VCLKC: length 1.4
  TOP w0.127: U9.11 v1(74.78,8.89)
VD0: length 100.2
  TOP w0.127: U5.K2 50.29,75.06 65.91,59.44 65.91,56.26 65.53,55.88 U6.2 62.74,55.88 60.83,53.98 60.83,44.58 63.25,42.16 64.26,42.16 65.79,40.64 65.79,39.62 65.53,39.37 U8.2 62.81,39.37 60.71,37.26 60.71,27.05 65.79,21.97 65.79,19.3 65.53,19.05 U9.2 51.69,19.05 v1(49.15,21.59)
  BOTTOM w0.127: R9.2 v1(49.15,21.59)
VD1: length 100.6
  TOP w0.127: U5.K3 51.56,74.17 66.17,59.56 66.17,55.24 65.53,54.61 U6.3 62.87,54.61 61.09,52.83 61.09,44.7 63.37,42.42 64.39,42.42 66.04,40.77 66.04,38.61 65.53,38.1 U8.3 62.81,38.1 60.96,36.25 60.96,27.18 66.04,22.1 66.04,18.29 65.53,17.78 U9.3 50.42,17.78 v1(49.15,19.05)
  BOTTOM w0.127: R13.2 v1(49.15,19.05)
VD2: length 101
  TOP w0.127: U5.K4 52.83,73.28 66.42,59.69 66.42,54.23 65.53,53.34 U6.4 62.87,53.34 61.34,51.82 61.34,44.83 63.5,42.67 64.52,42.67 66.29,40.89 66.29,37.59 65.53,36.83 U8.4 62.81,36.83 61.21,35.23 61.21,27.3 66.29,22.23 66.29,17.27 65.53,16.51 U9.4 v1(49.15,16.51)
  BOTTOM w0.127: R8.2 v1(49.15,16.51)
VD3: length 102.4
  TOP w0.127: v1(49.15,13.97) 50.42,15.24 U9.5 65.53,15.24 66.55,16.26 66.55,22.35 61.47,27.43 61.47,34.16 62.87,35.56 U8.5 65.53,35.56 66.55,36.58 66.55,41.02 64.64,42.93 63.63,42.93 61.59,44.96 61.59,50.8 62.87,52.07 U6.5 65.53,52.07 66.67,53.21 66.67,59.82 54.1,72.39 U5.K5
  BOTTOM w0.127: R12.2 v1(49.15,13.97)
VD4: length 103.9
  TOP w0.127: v1(49.15,11.43) 51.69,13.97 U9.6 65.53,13.97 66.8,15.24 66.8,22.48 61.72,27.56 61.72,33.15 62.87,34.29 U8.6 65.53,34.29 66.8,35.56 66.8,41.15 64.77,43.18 63.75,43.18 61.85,45.09 61.85,49.78 62.87,50.8 U6.6 65.53,50.8 66.93,52.2 66.93,59.94 55.37,71.5 U5.K6
  BOTTOM w0.127: R7.2 v1(49.15,11.43)
VD5: length 105.4
  TOP w0.127: U5.K7 56.64,70.61 67.18,60.07 67.18,51.18 65.53,49.53 U6.7 62.87,49.53 62.1,48.77 62.1,45.21 63.88,43.43 64.9,43.43 67.06,41.27 67.06,34.54 65.53,33.02 U8.7 62.87,33.02 61.98,32.13 61.98,27.69 67.06,22.61 67.06,14.22 65.53,12.7 U9.7 52.96,12.7 v1(49.15,8.89)
  BOTTOM w0.127: R11.2 v1(49.15,8.89)
